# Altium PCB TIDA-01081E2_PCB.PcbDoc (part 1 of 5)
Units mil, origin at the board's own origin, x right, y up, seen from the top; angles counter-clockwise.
Board outline 8611.33 x 3169.64 mil, 4 copper layers (Top Layer, VCC, GND, Bottom Layer), stack 61.6 mil thick; 411 components, 187 nets, 1087 pads, 1987 vias.
Unrouted connection lines stored in the file: 7.
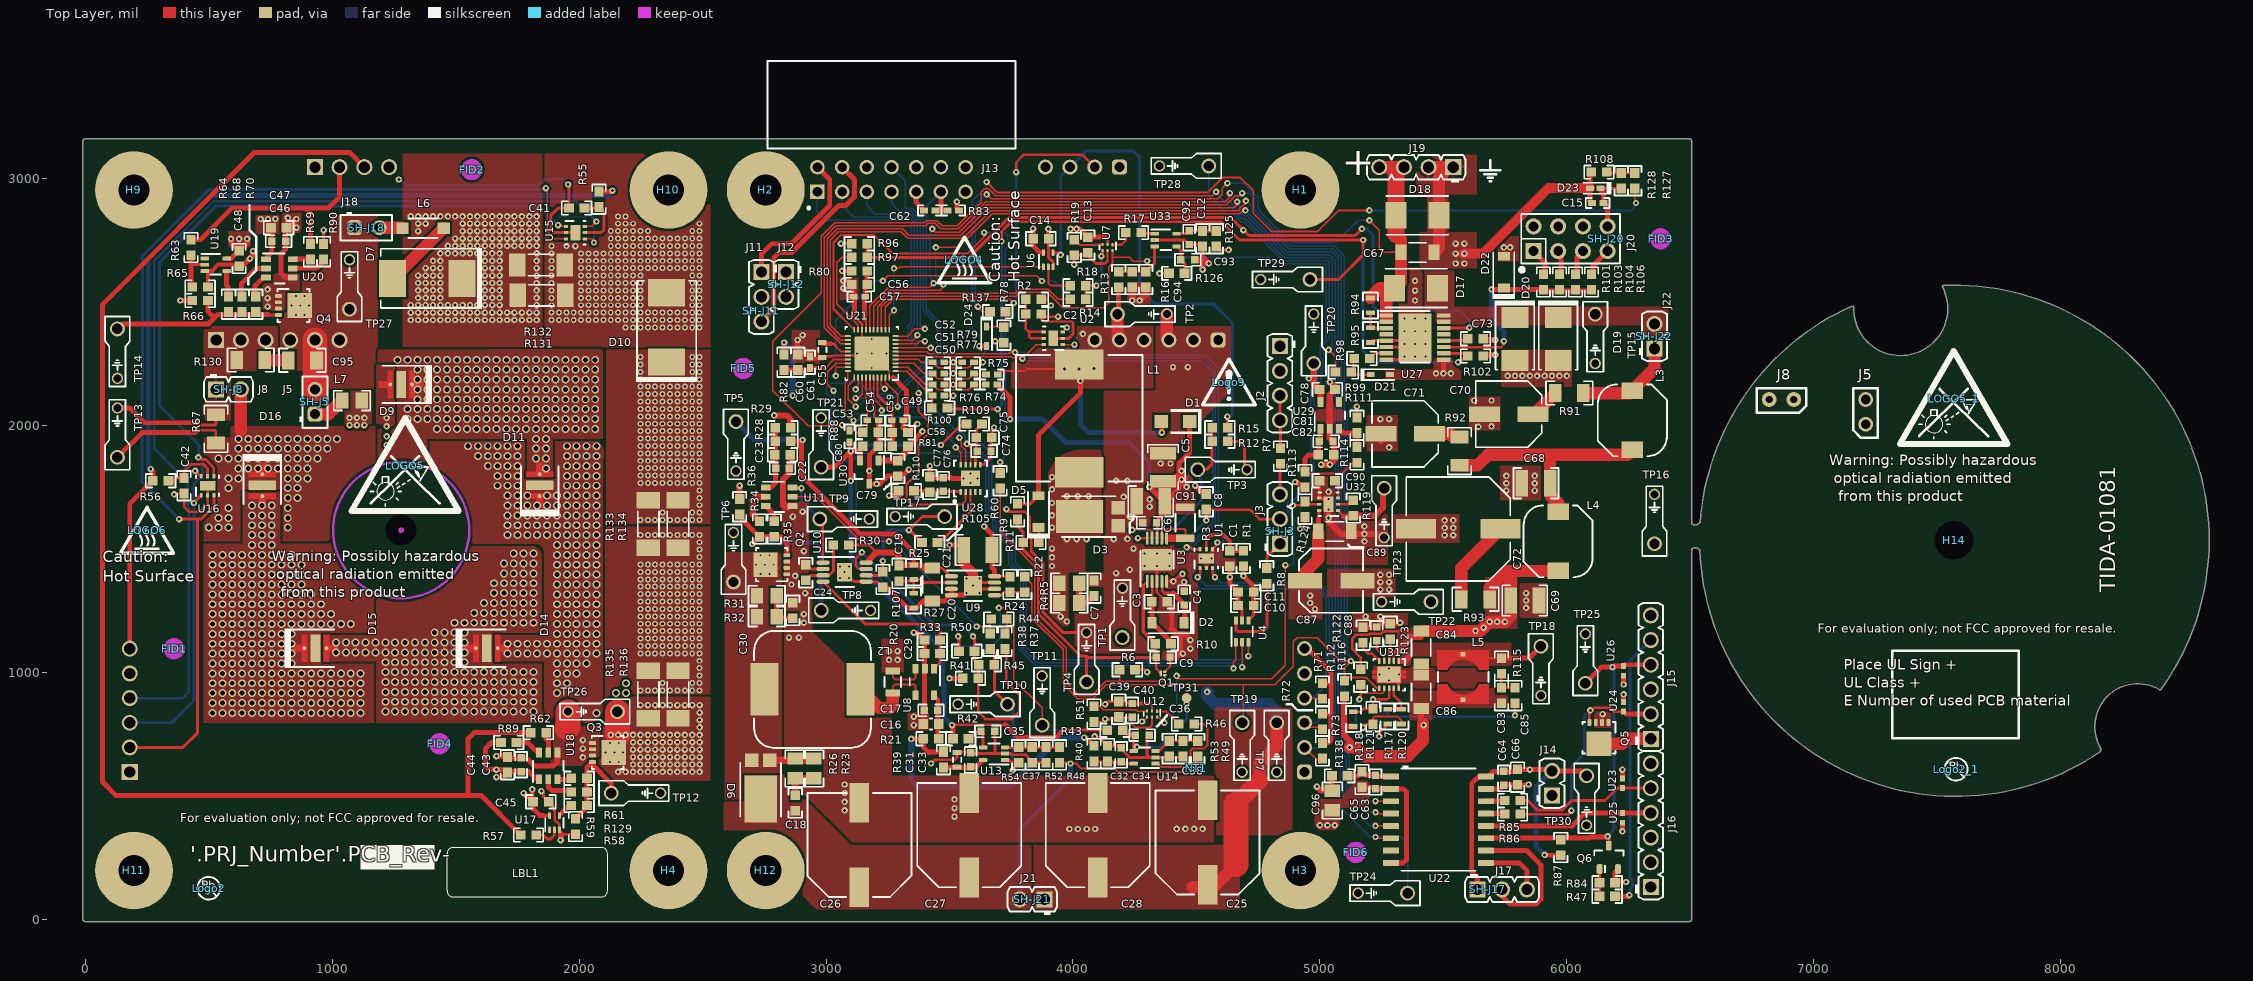
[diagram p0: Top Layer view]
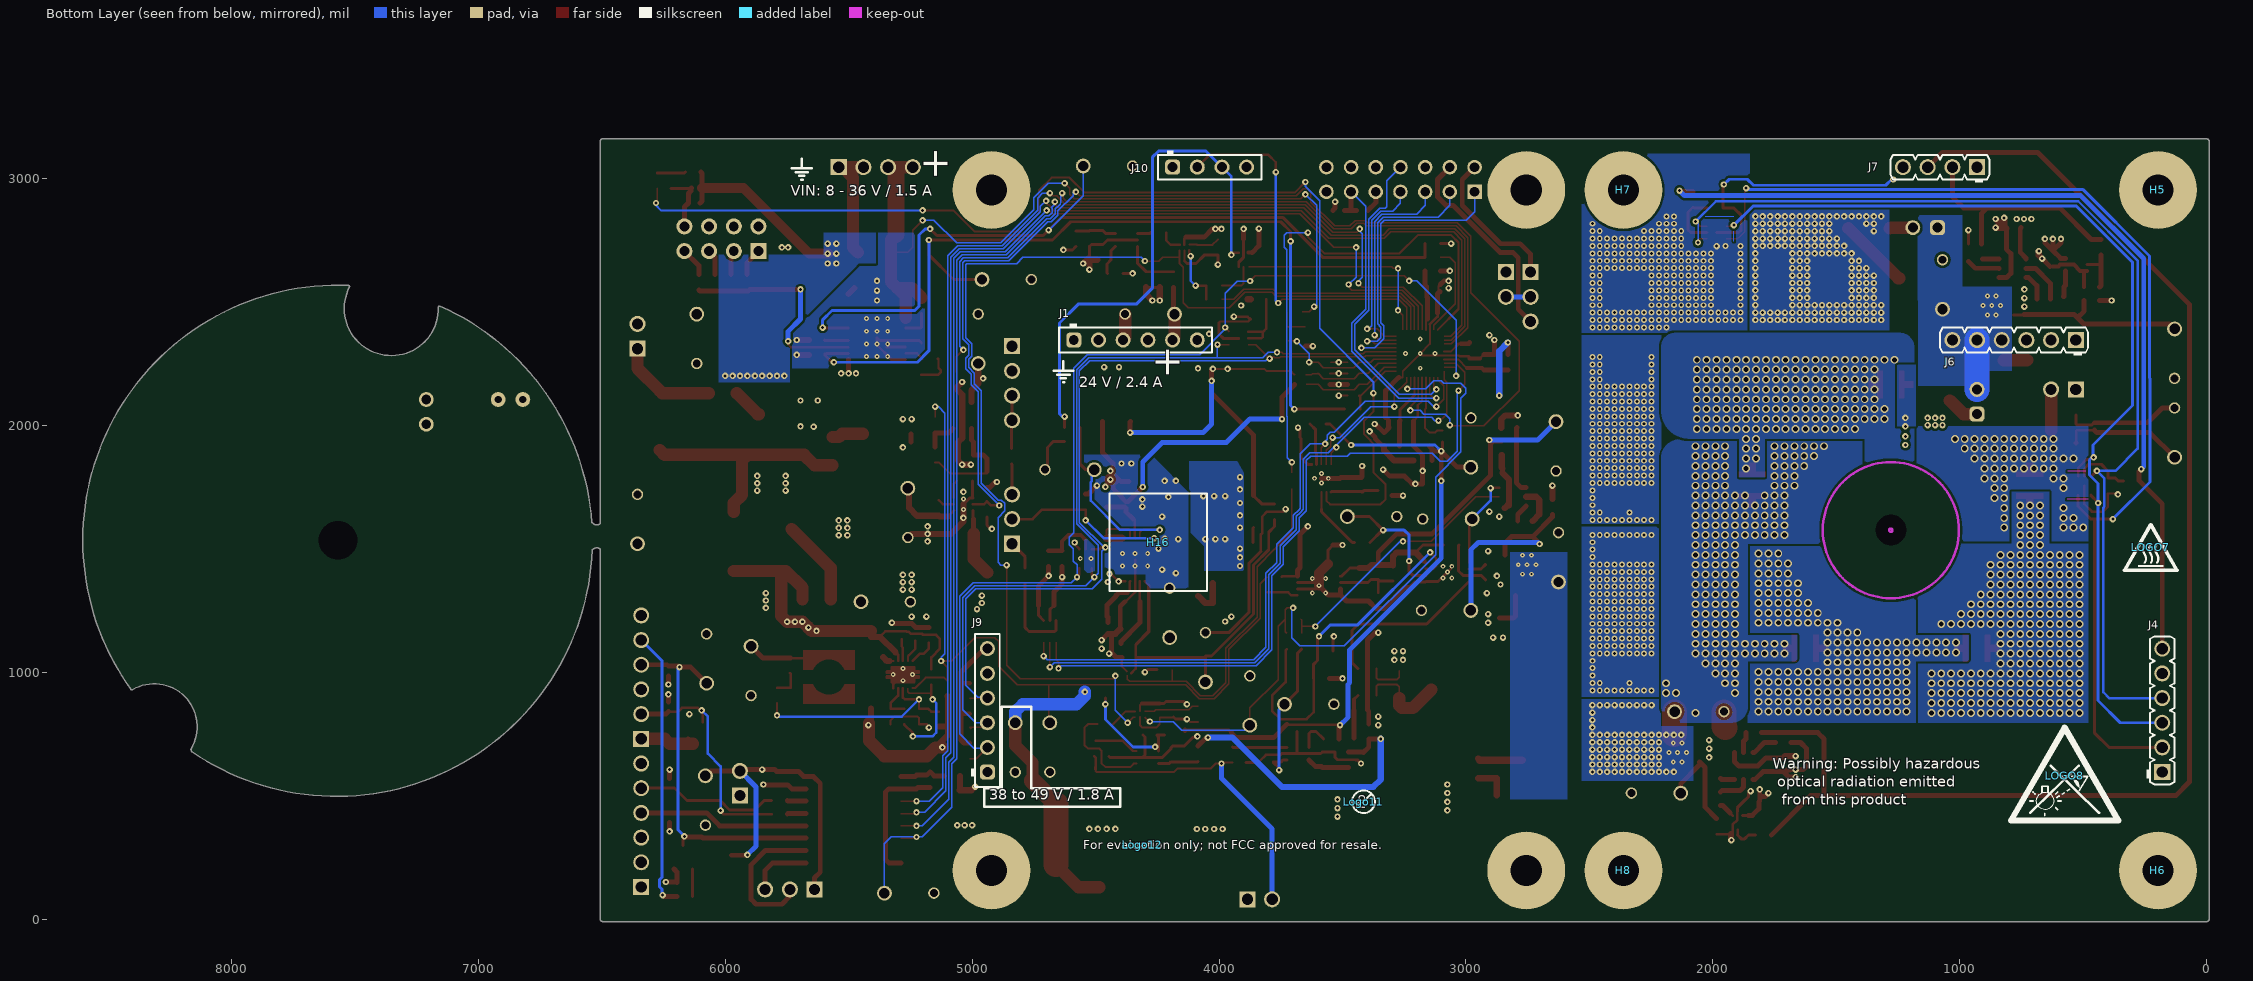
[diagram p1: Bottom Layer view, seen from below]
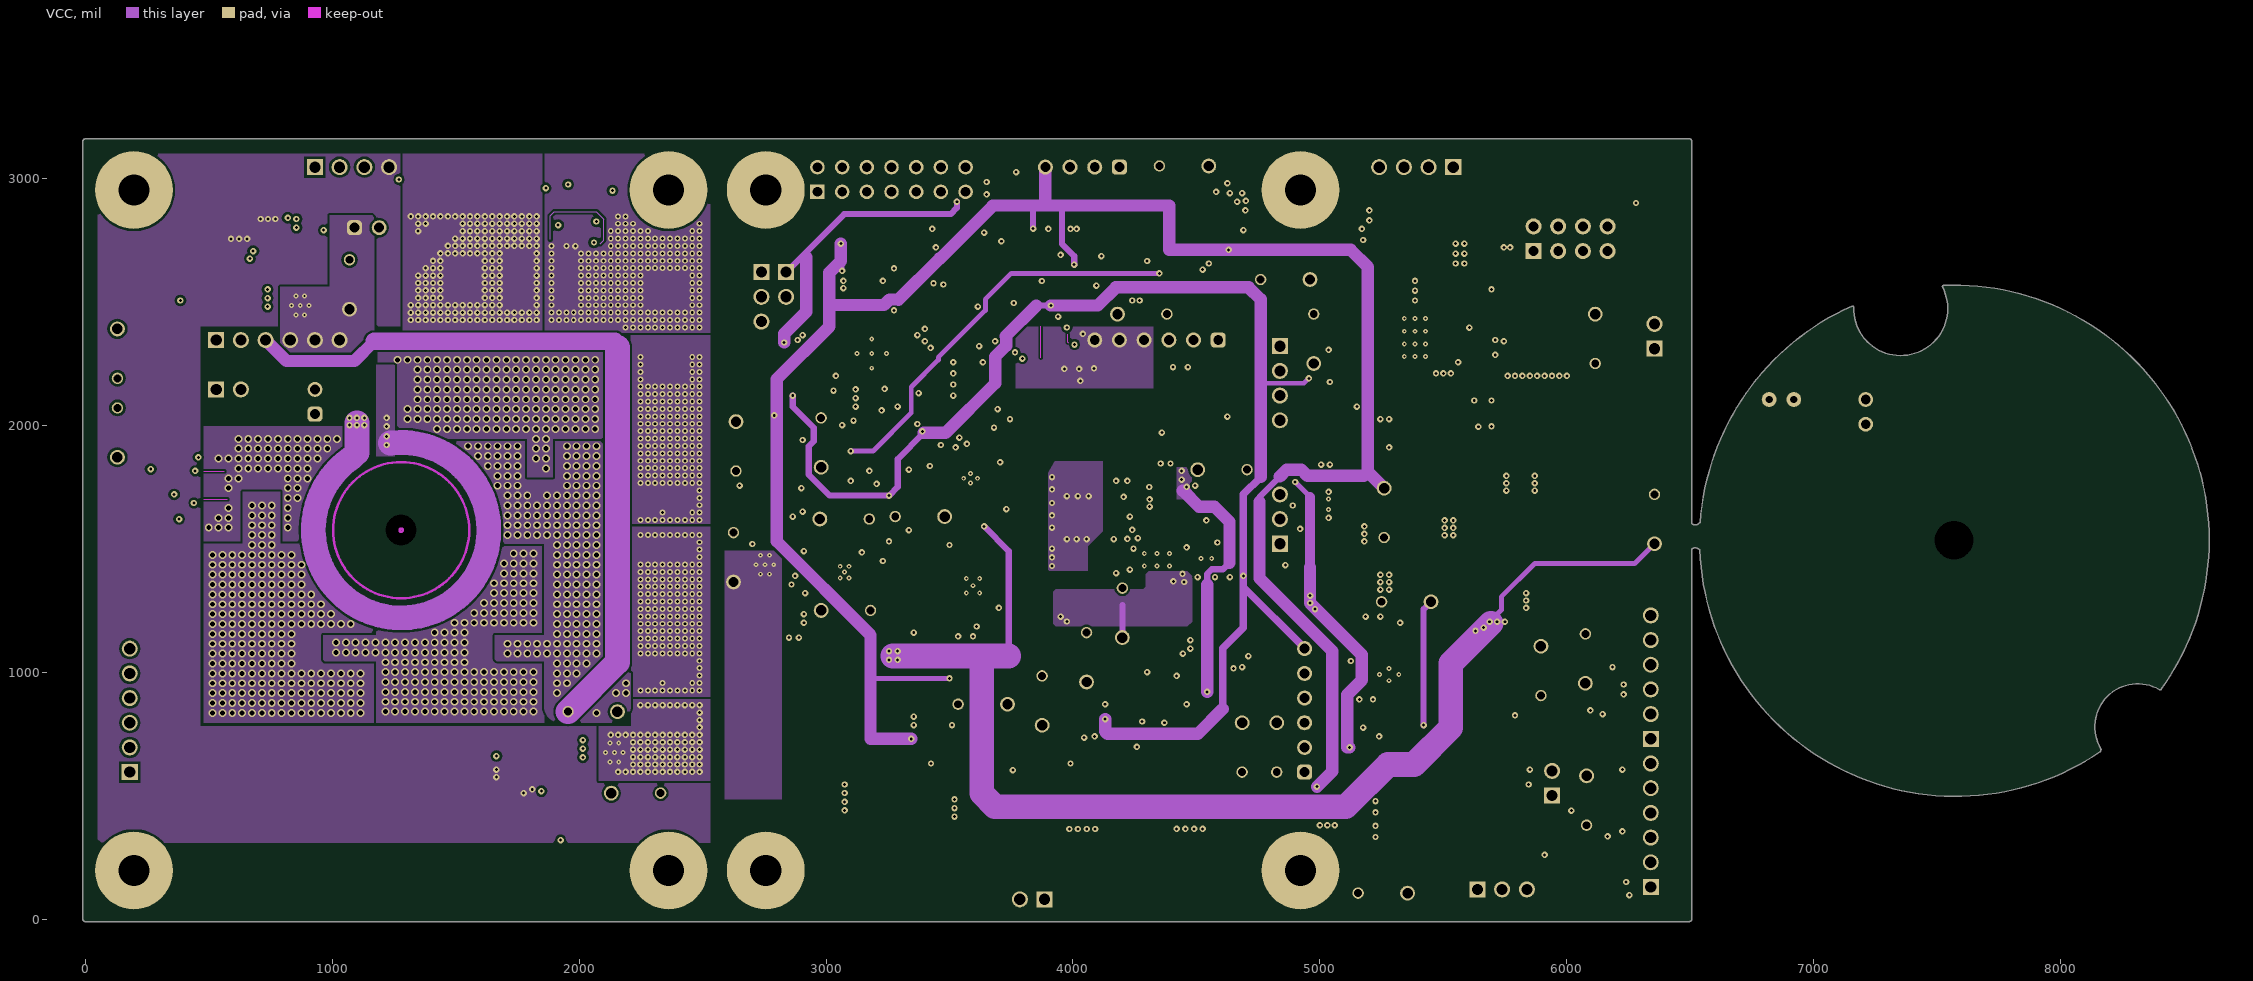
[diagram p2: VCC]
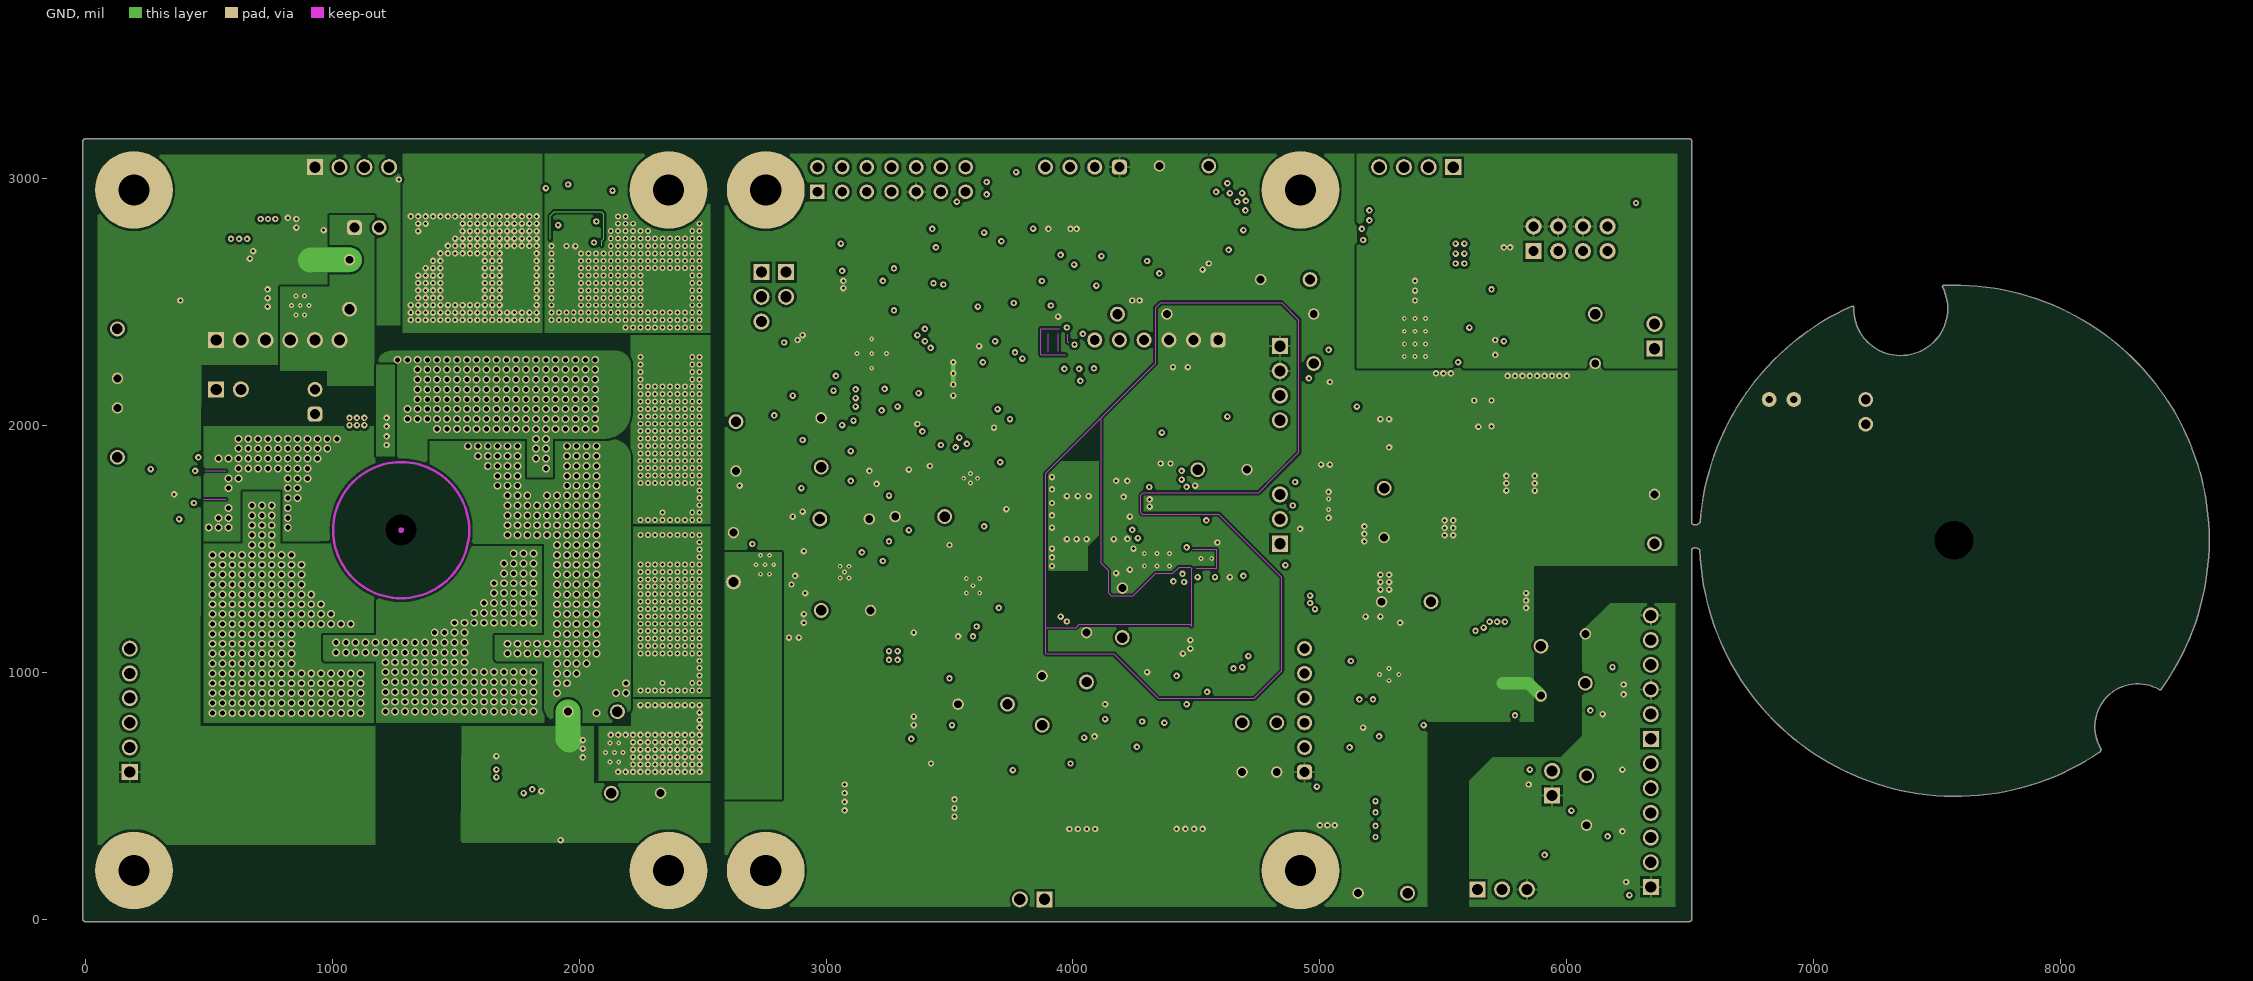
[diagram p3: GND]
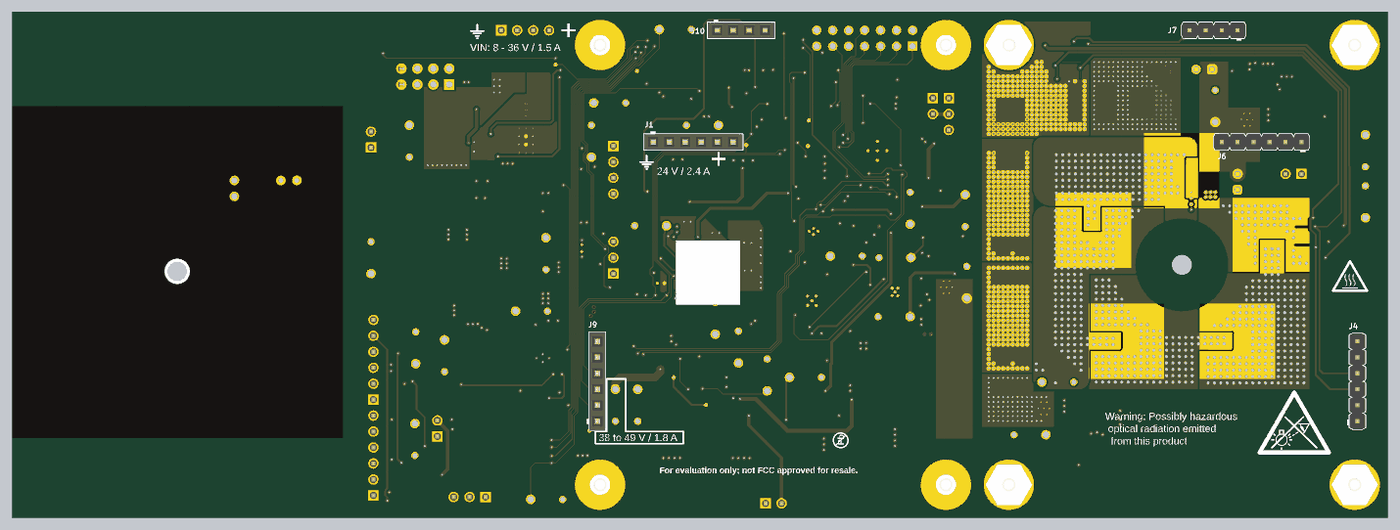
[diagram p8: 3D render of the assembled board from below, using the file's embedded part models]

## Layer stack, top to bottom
Top Solder: solder mask 0.4, Solder Resist, Dk 3.5
Top Layer: signal copper 1.4
Dielectric 1: prepreg 8, FR-4, Dk 4.2
VCC: signal copper 1.4
Dielectric 2: core 40, FR-4, Dk 4.2
GND: signal copper 1.4
Dielectric 3: prepreg 8, FR-4, Dk 4.2
Bottom Layer: signal copper 1.4
Bottom Solder: solder mask 0.4, Solder Resist, Dk 3.5

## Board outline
0,-10.02 cw(c0,0) -10.01,0 -10.01,3149.61 cw(c0,3149.61) 0,3159.62 6496.06,3159.62 cw(c6496.06,3149.61) 6506.08,3149.61 cw(c6496.06,3149.61) 6505.02,3145.12 6505.02,1602.2 ccw(c6520,1620) 6536.45,1603.55 cw(c6540,1600) 6540.18,1605.01 cw(c7574.8,1534.09) 7154.55,2482.16 cw(c7156.58,2477.58) 7161.6,2477.58 cw(c7156.58,2477.58) 7161.59,2477.42 ccw(c7352.06,2472.52) 7542.58,2472.52 ccw(c7352.06,2472.52) 7521.86,2558.93 ccw(c7352.06,2472.52) 7521.84,2558.96 7521.86,2558.93 cw(c7526.31,2561.23) 7526.11,2566.24 cw(c7568.3,1534.09) 8601.32,1534.09 cw(c7568.3,1534.09) 8407.12,931.17 cw(c8402.66,933.47) 8400.13,929.14 ccw(c8312.24,778.71) 8162.61,689.46 cw(c8158.3,686.89) 8163.31,686.89 cw(c8158.3,686.89) 8161.27,682.85 cw(c8156.42,681.56) 8161.44,681.56 cw(c8156.42,681.56) 8159.25,677.42 cw(c7574.8,1534.09) 6538.49,1495.22 cw(c6540,1500) 6536.45,1496.45 ccw(c6520,1480) 6505.02,1497.8 6505.02,4.49 cw(c6496.06,0) 6506.08,0 cw(c6496.06,0) 6496.06,-10.02

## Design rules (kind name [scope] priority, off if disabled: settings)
AcuteAngle [All] p1: minimum=1.50000000000000E+0001 checktracksonly=FALSE
AssemblyTestPointUsage [All] p1: valid=2
BoardOutlineClearance BoardOutlineClearance_MountingHoles [OnCopper and InComponentClass('Mounting Holes')] p1: gap=30 ignorepadtopadclearanceinfootprint=FALSE
BoardOutlineClearance BoardOutlineClearance_Poly [OnCopper and IsPoly] p2: gap=25 ignorepadtopadclearanceinfootprint=FALSE
BoardOutlineClearance [OnCopper and Not InComponentClass('Logo') and not InComponentClass('FiducialMark') and not InRegion(1000,500,4000,800) and not InPoly] p3: gap=30 ignorepadtopadclearanceinfootprint=FALSE
Clearance Clearance_fiducial [IsKeepOut and InComponentClass('FiducialMark') vs IsPad and InComponentClass('FiducialMark')] p1: gap=0 ignorepadtopadclearanceinfootprint=FALSE
Clearance Clearance_q1 [InComponent('Q1')] p2: gap=3 ignorepadtopadclearanceinfootprint=FALSE except(0: Arc-Hole Track-Hole SMDPad-Hole THPad-Hole Via-Hole Fill-Hole Poly-Hole Region-Hole Text-Hole)
Clearance Clearance_Keepouts [((IsTrack Or IsArc) And Not InPoly) And IsFree and IsKeepOut vs ((IsTrack Or IsArc) And Not InPoly) And IsFree and IsKeepOut] p3: gap=0 ignorepadtopadclearanceinfootprint=FALSE
Clearance Clearance_Poly [InPolygon] p4: gap=10 ignorepadtopadclearanceinfootprint=FALSE except(0: Arc-Hole Track-Hole SMDPad-Hole THPad-Hole Via-Hole Fill-Hole Poly-Hole Region-Hole Text-Hole)
Clearance [All] p5: gap=6 ignorepadtopadclearanceinfootprint=FALSE except(0: Arc-Hole Track-Hole SMDPad-Hole THPad-Hole Via-Hole Fill-Hole Poly-Hole Region-Hole Text-Hole)
ComponentClearance ComponentClearance_screws [InComponent('H*')] p1: gap=0 collisioncheckmode=3 verticalgap=0 showdistances=FALSE
ComponentClearance ComponentClearance_shj12 [InComponent('SH-J12')] p2: gap=0 collisioncheckmode=3 verticalgap=0 showdistances=FALSE
ComponentClearance ComponentClearance_j11 [InComponent('J11')] p3: gap=0 collisioncheckmode=3 verticalgap=0 showdistances=FALSE
ComponentClearance ComponentClearance_j13 [InComponent('J13')] p4: gap=0 collisioncheckmode=3 verticalgap=0 showdistances=FALSE
ComponentClearance ComponentClearance_j17 [InComponent('J17')] p5: gap=0 collisioncheckmode=3 verticalgap=0 showdistances=FALSE
ComponentClearance ComponentClearance_j15 [InComponent('J15')] p6: gap=0 collisioncheckmode=3 verticalgap=0 showdistances=FALSE
ComponentClearance ComponentClearance_j16 [InComponent('J16')] p7: gap=0 collisioncheckmode=3 verticalgap=0 showdistances=FALSE
ComponentClearance ComponentClearance_MountingHoles_FiducialMarks [InComponentClass('Mounting Holes') vs InComponentClass('FiducialMark')] p8: gap=50 collisioncheckmode=3 verticalgap=10 showdistances=FALSE
ComponentClearance ComponentClearance_Shunt [InComponentClass('Header') vs InComponentClass('Shunt')] p9: gap=0 collisioncheckmode=3 verticalgap=0 showdistances=FALSE
ComponentClearance ComponentClearance_Logo [InComponentClass('Logo')] p10: gap=50 collisioncheckmode=3 verticalgap=10 showdistances=FALSE
ComponentClearance ComponentClearance_ScrewToNut [(HasFootprint('NY PMS 440 0025 PH')) vs (HasFootprint('Keystone_1902C'))] p11: gap=5 collisioncheckmode=3 verticalgap=10 showdistances=FALSE
ComponentClearance ComponentClearance_MountingHoles [InComponentClass('Mounting Holes')] p12: gap=30 collisioncheckmode=3 verticalgap=100000 showdistances=FALSE
ComponentClearance ComponentClearance_SmallPassives [HasFootprint('0201*') or HasFootprint('0402*') or HasFootprint('0508') or HasFootprint('0603*') or HasFootprint('0612') or HasFootprint('0805*') or HasFootprint('0815*') or HasFootprint('0830*') or HasFootprint('1206*') or HasFootprint('1210*') or HasFootprint('1808*') or HasFootprint('1812*') or HasFootprint('1825*') or HasFootprint('2010*') or HasFootprint('2220*') or HasFootprint('2225*') or HasFootprint('2512*') or HasFootprint('2728*') or HasFootprint('3518*') vs HasFootprint('0201*') or HasFootprint('0402*') or HasFootprint('0508') or HasFootprint('0603*') or HasFootprint('0612') or HasFootprint('0805*') or HasFootprint('0815*') or HasFootprint('0830*') or HasFootprint('1206*') or HasFootprint('1210*') or HasFootprint('1808*') or HasFootprint('1812*') or HasFootprint('1825*') or HasFootprint('2010*') or HasFootprint('2220*') or HasFootprint('2225*') or HasFootprint('2512*') or HasFootprint('2728*') or HasFootprint('3518*')] p13: gap=14.96 collisioncheckmode=3 verticalgap=10 showdistances=FALSE
ComponentClearance ComponentClearance_THtoSMT [IsThruComponent vs IsSMTComponent] p14: gap=30 collisioncheckmode=3 verticalgap=30 showdistances=FALSE
ComponentClearance ComponentClearance_THtoTH [IsThruComponent vs IsThruComponent] p15: gap=30 collisioncheckmode=3 verticalgap=30 showdistances=FALSE
ComponentClearance [All] p16: gap=30 collisioncheckmode=3 verticalgap=10 showdistances=FALSE
DiffPairsRouting [All] p1: maxlimit=100 minlimit=10 mostfreqgap=10 toplayer_minwidth=15 toplayer_maxwidth=15 toplayer_prefwidth=15 midlayer1_minwidth=15 midlayer1_maxwidth=15 midlayer1_prefwidth=15 midlayer2_minwidth=15 midlayer2_maxwidth=15 midlayer2_prefwidth=15 bottomlayer_minwidth=15 bottomlayer_maxwidth=15 bottomlayer_prefwidth=15 maxuncoupledlength=1000
FabricationTestPointUsage TestPointUsage [All] p1: valid=2 allowmultiple=FALSE
FabricationTestpoint Testpoint [All] p1: side=3 testpointundercomponent=TRUE minsize=40 maxsize=100 preferedsize=60 minholesize=0 maxholesize=40 preferedholesize=32 testpointgrid=1 allowsidetop=TRUE allowsidebottom=TRUE usegrid=TRUE gridtolerance=0.01
FanoutControl Fanout_LCC [IsLCC] p1: bgadir=Out bgaviamode=Centered fanoutstyle=Auto fanoutdirection=Alternating viagrid=1 // Fanout_LCC (Default Rule)
FanoutControl Fanout_BGA [IsBGA] p2: bgadir=Out bgaviamode=Centered fanoutstyle=Auto fanoutdirection=Alternating viagrid=1 // Fanout_BGA (Default Rule)
FanoutControl Fanout_Default [All] p4: bgadir=Out bgaviamode=Centered fanoutstyle=Auto fanoutdirection=Alternating viagrid=1 // Fanout_Default (Default Rule)
FanoutControl Fanout_Small [(CompPinCount < 5)] p5: bgadir=Out bgaviamode=Centered fanoutstyle=Auto fanoutdirection=OutThenIn viagrid=1 // Fanout_Small (Default Rule)
HoleSize [All] p1: absolutevalues=TRUE maxlimit=251 minlimit=7.87 maxpercent=80.000 minpercent=20.000
MinimumAnnularRing MinimumAnnularRing_ThermalPadVias [IsVia and InAnyComponent] p1: minimumring=5.91
MinimumAnnularRing [All] p2: minimumring=6
MinimumSolderMaskSliver MinimumSolderMaskSliver_Logo [InComponentClass('Logo') vs InComponentClass('Logo')] p1: minsoldermaskwidth=0.7
MinimumSolderMaskSliver [All] p2: minsoldermaskwidth=3
PlaneConnect [All] p1: planeconnectstyle=Direct reliefexpansion=10 reliefentries=4 reliefconductorwidth=10 reliefairgap=10
PolygonConnect PolygonConnect_j22 [InComponent('J22')] p1: connectstyle=Direct reliefconductorwidth=10 reliefentries=4 polygonreliefangle="90 Angle" airgapwidth=10
PolygonConnect PolygonConnect_j21 [InComponent('J21');] p2: connectstyle=Direct reliefconductorwidth=10 reliefentries=4 polygonreliefangle="90 Angle" airgapwidth=10
PolygonConnect PolygonConnect_j18 [InComponent('J18');] p3: connectstyle=Direct reliefconductorwidth=10 reliefentries=4 polygonreliefangle="90 Angle" airgapwidth=10
PolygonConnect PolygonConnect_j6 [InComponent('J6');] p4: connectstyle=Direct reliefconductorwidth=10 reliefentries=4 polygonreliefangle="90 Angle" airgapwidth=10
PolygonConnect PolygonConnect_j7 [InComponent('J7');] p5: connectstyle=Direct reliefconductorwidth=10 reliefentries=4 polygonreliefangle="90 Angle" airgapwidth=10
PolygonConnect PolygonConnect_j1 [InComponent('J1');] p6: connectstyle=Direct reliefconductorwidth=10 reliefentries=4 polygonreliefangle="90 Angle" airgapwidth=10
PolygonConnect PolygonConnect_tp [InComponent('TP*');] p7: connectstyle=Direct reliefconductorwidth=10 reliefentries=4 polygonreliefangle="90 Angle" airgapwidth=10
PolygonConnect PolygonConnect_buckvout [InNet('BUCK_VOUT')] p8: connectstyle=Direct reliefconductorwidth=10 reliefentries=4 polygonreliefangle="90 Angle" airgapwidth=10
PolygonConnect PolygonConnect_THT [All vs IsThruPin] p9: connectstyle=Relief reliefconductorwidth=10 reliefentries=4 polygonreliefangle="90 Angle" airgapwidth=10
PolygonConnect [All] p10: connectstyle=Direct reliefconductorwidth=10 reliefentries=4 polygonreliefangle="90 Angle" airgapwidth=10
RoutingVias ThermalPadVias [IsVia and InAnyComponent] p1: holewidth=7.87 width=19.68 viastyle="Through Hole" minholewidth=7.87 minwidth=19.68 maxholewidth=12.99 maxwidth=23.62
RoutingVias [All] p2: holewidth=12 width=26 viastyle="Through Hole" minholewidth=8 minwidth=24 maxholewidth=40 maxwidth=65
SilkToBoardRegionClearance [Not ((IsComment or IsDesignator) And (Hide <> 'False')) and not InRegion(1000,500,4000,800)] p1:
SilkToSilkClearance SilkToSilkClearance_Pb-FreeLogo [(HasFootprint('Pb-Free_Overlay_Medium') OR HasFootprint('Pb-Free_Overlay_Small')) vs (HasFootprint('Pb-Free_Overlay_Medium') OR HasFootprint('Pb-Free_Overlay_Small'))] p1: silktosilkclearance=0
SilkToSilkClearance [All] p2: silktosilkclearance=2
SilkToSolderMaskClearance SilkToComponentPadClearance [(IsPad or IsFill or IsRegion) and InAnycomponent] p1: minsilkscreentomaskgap=2 clearancetoexposedcopper=TRUE
SilkToSolderMaskClearance "Silk to Solder Mask Opening" [All] p2: minsilkscreentomaskgap=2 clearancetoexposedcopper=FALSE
SolderMaskExpansion SolderMaskExpansion_via [IsVia] p1: expansion=-8
SolderMaskExpansion [All] p2: expansion=2
Width [All] p1: maxlimit=100 minlimit=6 preferedwidth=10 checkconnectedcopper=TRUE
15 further rules are at their usual default settings.

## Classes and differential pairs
component class TIDA-01081E2_CommonPower: C15 C67 C68 C69 C70 C71 C72 C73 C74 C75 C76 C77 C78 C79 C80 C81 C82 C83 C84 C85 C86 C87 C88 C89 C90 D17 D18 D19 D20 D21 D22 D23 J19 J20 J22 L3 L4 L5 R91 R92 R93 R94 R95 R96 R97 R98 R99 R100 R101 R102 R103 R104 R105 R106 R107 R108 R109 R110 R111 R112 R113 R114 R115 R116 R117 R118 R119 R120 R121 R122 R123 R124 R127 R128 SH-J20 SH-J22 TP15 TP16 TP17 TP18 TP19 TP20 TP21 TP22 TP23 TP28 TP29 U27 U28 U29 U30 U31 U32
component class TIDA-01081E2_DigitalIO: C63 C64 C65 C66 C96 J14 J15 J16 J17 Q5 Q6 R47 R84 R85 R86 R87 R138 SH-J17 TP24 TP25 TP30 U22 U23 U24 U25 U26
component class TIDA-01081E2_Controller: C49 C50 C51 C52 C53 C54 C55 C56 C57 C58 C59 C60 C61 C62 D24 J9 J10 J11 J12 J13 R71 R72 R73 R74 R75 R76 R77 R78 R79 R80 R81 R82 R83 R88 R137 SH-J11 SH-J12 U21
component class TIDA-01081E2_LED_Board: C41 C42 C43 C44 C45 C46 C47 C48 C95 D7 D9 D10 D11 D14 D15 D16 J4 J5 J6 J7 J8 J18 L6 L7 Q3 Q4 R55 R56 R57 R58 R59 R61 R62 R63 R64 R65 R66 R67 R68 R69 R70 R89 R90 R129 R130 R131 R132 R133 R134 R135 R136 SH-J5 SH-J8 SH-J18 TP12 TP13 TP14 TP26 TP27 U15 U16 U17 U18 U19 U20
component class TIDA-01081E2_Pre-Boost: C16 C17 C18 C19 C20 C21 C22 C23 C24 C25 C26 C27 C28 C29 C30 C31 C32 C33 C34 C35 C36 C37 C38 C39 C40 D6 J21 L2 NT1 Q2 R20 R21 R22 R23 R24 R25 R26 R27 R28 R29 R30 R31 R32 R33 R34 R35 R36 R37 R38 R39 R40 R41 R42 R43 R44 R45 R46 R48 R49 R50 R51 R52 R53 R54 SH-J21 TP5 TP6 TP7 TP8 TP9 TP10 TP11 TP31 U8 U9 U10 U11 U12 U13 U14
component class Shunt: SH-J3 SH-J5 SH-J8 SH-J11 SH-J12 SH-J17 SH-J18 SH-J20 SH-J21 SH-J22
component class Header: J2 J3 J4 J5 J6 J7 J8 J11 J12 J14 J15 J16 J17 J18 J19 J20 J21 J22
component class Label: LBL1
component class AssemblyNote: ZZ1 ZZ2 ZZ3 ZZ4 ZZ5 ZZ6 ZZ7 ZZ8 ZZ9 ZZ10 ZZ11 ZZ12 ZZ13 ZZ14 ZZ?
component class FiducialMark: FID1 FID2 FID3 FID4 FID5 FID6
component class TIDA-01081E2_EVM_Hardware: FID1 FID2 FID3 FID4 FID5 FID6 H1 H2 H3 H4 H5 H6 H7 H8 H9 H10 H11 H12 H14 LBL1 Logo2 Logo3 LOGO4 LOGO5 LOGO6 LOGO7 LOGO8 Logo9 LOGO10 Logo11 Logo12 ZZ1 ZZ2 ZZ3 ZZ4 ZZ5 ZZ6 ZZ7 ZZ8 ZZ9 ZZ10 ZZ11 ZZ12 ZZ13 ZZ14 ZZ?
component class TIDA-01081E2_LED_Buck: C1 C2 C3 C4 C5 C6 C7 C8 C9 C10 C11 C12 C13 C14 C91 C92 C93 C94 D1 D2 D3 D5 H16 J1 J2 J3 L1 Q1 R1 R2 R3 R4 R5 R6 R7 R8 R9 R10 R11 R12 R13 R14 R15 R16 R17 R18 R19 R60 R125 R126 SH-J3 TP1 TP2 TP3 TP4 U1 U2 U3 U4 U6 U7 U33

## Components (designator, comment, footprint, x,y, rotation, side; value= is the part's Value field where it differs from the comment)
C1 "GRM188R71C105KE15D" 0603 4635,1460 r270 top value=1uF
C2 "GRM188R71C105KE15D" 0603 3840,2450 r0 top value=1uF
C3 "GRM188R71C105KE15D" 0603 4350,1285 r0 top value=1uF
C4 "GCM188R71C104KA37J" 0603_HV 4450,1300 r270 top value=0.1uF
C5 "GRM32ER71K475KE14L" 1210_270 4365,1830 r90 top value=4.7uF
C6 "GRM188R72A104KA35D" 0603_HV 4310,1605 r180 top value=0.1uF
C7 "CGA3E2X7R2A222K080AA" 0603 4085,1340 r90 top value=2200pF
C8 "GCM1885C1H471JA16D" 0603 4540,1690 r90 top value=470pF
C9 "GCM1885C1H471JA16D" 0603_HV 4365,1060 r0 top value=470pF
C10 "C0603C104K8RACTU" 0603 4700,1270 r180 top value=0.1uF
C11 "GRM188Z71A106MA73D" 0603 4700,1325 r180 top value=10uF
C12 "GRM188R71C105KE15D" 0603 4525,2755 r90 top value=1uF
C13 "GRM188R71C105KE15D" 0603 4060,2730 r270 top value=1uF
C14 "GRM188R71C105KE15D" 0603 3870,2755 r180 top value=1uF
C15 "C1005X7R1C103K050BA" 0402 6125,2900 r180 top value=0.01uF
C16 "ZRB18AD71A106KE01L" 0603_120 3425,790 r180 top value=10uF
C17 "GCM188R71C104KA37J" 0603_HV 3425,845 r0 top value=0.1uF
C18 "CGA3E2X7R2A222K080AA" 0603 2875,470 r270 top value=2200pF
C19 "CL10B103KB8NCNC" 0603 3295,1400 r270 top value=0.01uF
C20 "GRM31CR61E226KE15L" 1206_180 3430,1355 r270 top value=22uF
C21 "GRM32ER71K475KE14L" 1210_270 3615,1495 r180 top value=4.7uF
C22 "GCM188R71C104KA37J" 0603_HV 2823.5,1825 r180 top value=0.1uF
C23 "GRM188R71C105KE15D" 0603 2823.5,1880 r180 top value=1uF
C24 "GRM188R71C105KE15D" 0603 2917.59,1403.19 r90 top value=1uF
C25 "EEE-FK1J101P" SM_RADIAL_G 4545,310 r90 top value=100uF
C26 "EEE-FK1J101P" SM_RADIAL_G 3135,300 r90 top value=100uF
C27 "EEE-FK1J101P" SM_RADIAL_G 3580,340 r90 top value=100uF
C28 "EEE-FK1J101P" SM_RADIAL_G 4100,340 r90 top value=100uF
C29 "CGA3E2C0G1H470J080AA" 0603 3430,1075 r180 top value=47pF
C30 "CGA3E2X7R2A222K080AA" 0603 2865,1250 r90 top value=2200pF
C31 "GRM188R71C105KE15D" 0603S 3530.31,645 r270 top value=1uF
C32 "GRM188R71C105KE15D" 0603 4140,670 r270 top value=1uF
C33 "GCM188R71C104KA37J" 0603_HV 3585.31,645 r270 top value=0.1uF
C34 "GCM188R71C104KA37J" 0603_HV 4195,665 r270 top value=0.1uF
C35 "GCM188R71C104KA37J" 0603_HV 3655.31,760 r0 top value=0.1uF
C36 "GCM188R71C104KA37J" 0603_HV 4280,745 r0 top value=0.1uF
C37 "C0603C151J5GACTU" 0603 3835,665 r90 top value=150pF
C38 "06035A101JAT2A" 0603 4390,690 r90 top value=100pF
C39 "GRM188R71C105KE15D" 0603 4185,850 r270 top value=1uF
C40 "GCM188R71C104KA37J" 0603_HV 4240,845 r90 top value=0.1uF
C41 "GRM188R71C105KE15D" 0603 1990,2880 r180 top value=1uF
C42 "GRM188R71C105KE15D" 0603 400,1755 r270 top value=1uF
C43 "GCM188R71C104KA37J" 0603_HV 1765,625 r270 top value=0.1uF
C44 "GRM188R71C105KE15D" 0603 1710,625 r270 top value=1uF
C45 "GRM188R71C105KE15D" 0603 1845,475 r180 top value=1uF
C46 "GCM188R71C104KA37J" 0603_HV 783.11,2745 r180 top value=0.1uF
C47 "GRM188R71C105KE15D" 0603 783.11,2800 r180 top value=1uF
C48 "GRM188R71C105KE15D" 0603 623.11,2675 r90 top value=1uF
C49 "C1005X7R1C103K050BA" 0402 3455,2120 r0 top value=0.01uF
C50 "C1005X7R1C103K050BA" 0402 3455,2165 r0 top value=0.01uF
C51 "C1005X7R1C103K050BA" 0402 3455,2210 r0 top value=0.01uF
C52 "C1005X7R1C103K050BA" 0402 3455,2255 r0 top value=0.01uF
C53 "GRM188Z71A106MA73D" 0603 3180,1971.3 r0 top value=10uF
C54 "GRM155R71A104KA01D" 0402 3190,2020 r180 top value=0.1uF
C55 "GRM188R70J474KA01D" 0603S 2985,2305 r270 top value=0.47uF
C56 "GRM188Z71A106MA73D" 0603 3135,2570 r180 top value=10uF
C57 "GRM155R71A104KA01D" 0402 3135,2520 r0 top value=0.1uF
C58 "GRM188Z71A106MA73D" 0603 3300,1970 r0 top value=10uF
C59 "GRM155R71A104KA01D" 0402 3290,2020 r180 top value=0.1uF
C60 "GRM188Z71A106MA73D" 0603 2885,2255 r90 top value=10uF
C61 "GRM155R71A104KA01D" 0402 2935,2255 r270 top value=0.1uF
C62 "GRM155R70J222KA01D" 0402 3420,2870 r180 top value=2200pF
C63 "GCM188R71C104KA37J" 0603_HV 5225,555 r90 top value=0.1uF
C64 "GCM188R71C104KA37J" 0603_HV 5745,570 r90 top value=0.1uF
C65 "GRM188Z71A106MA73D" 0603 5170,565 r270 top value=10uF
C66 "GRM188Z71A106MA73D" 0603 5800,575 r270 top value=10uF
C67 "GRM31CR72A105KA01L" 1206_180 5395,2700 r0 top value=1uF
C68 "GRM32ER71K475KE14L" 1210_270 5875,1765 r180 top value=4.7uF
C69 "GRM32ER71K475KE14L" 1210_270 5830,1290 r0 top value=4.7uF
C70 "EEE-FK1J220XP" SM_RADIAL_D8 5765,2045 r180 top value=22uF
C71 "EEE-FK1J220XP" SM_RADIAL_D8 5345,1965 r180 top value=22uF
C72 "EEE-FK1J101P" SM_RADIAL_G 5560,1580 r180 top value=100uF
C73 "GRM188R71C105KE15D" 0603 5630,2350 r180 top value=1uF
C74 "GCM188R71C104KA37J" 0603_HV 3640,1895 r180 top value=0.1uF
C75 "GRM188R71C105KE15D" 0603 3640,1950 r180 top value=1uF
C76 "GCM188R71C104KA37J" 0603_HV 3475,1760 r270 top value=0.1uF
C77 "GRM188R71C105KE15D" 0603 3420,1760 r270 top value=1uF
C78 "GRM188R71C105KE15D" 0603 5030,2145 r0 top value=1uF
C79 "GRM188R71C105KE15D" 0603 3290,1825 r270 top value=1uF
C80 "GRM188R71C105KE15D" 0603 3180,1915 r0 top value=1uF
C81 "GCM188R71C104KA37J" 0603_HV 5025,1935 r180 top value=0.1uF
C82 "ZRB18AD71A106KE01L" 0603_120 5025,1880 r0 top value=10uF
C83 "C0603C561J5GACTU" 0603 5735,905 r90 top value=560pF
C84 "GRM31CR72A105KA01L" 1206_180 5410,1100 r270 top value=1uF
C85 "C0603C681J5GACTU" 0603 5790,905 r270 top value=680pF
C86 "C3216X5R1E336M160AC" 1206_180 5410,920 r90 top value=33uF
C87 "UUD1A101MCL1GS" SM_RADIAL_6.3AMM 5045,1370 r0 top value=100uF
C88 "GCM188R71C104KA37J" 0603_HV 5230,1155 r270 top value=0.1uF
C89 "C3216X5R1E336M160AC" 1206_180 5060,1570 r0 top value=33uF
C90 "GRM188R71C104KA01D" 0603 5030,1775 r180 top value=0.1uF
C91 "CGA6N3X7R2A225K230AB" 1210_250 4315,1692 r180 top value=2.2uF
C92 "GCM188R71C104KA37J" 0603_HV 4470,2760 r90 top value=0.1uF
C93 "GCM188R71C104KA37J" 0603_HV 4465,2670 r0 top value=0.1uF
C94 "06035A100JAT2A" 0603 4295,2590 r90 top value=10pF
C95 "12061A681JAT2A" 1206 879,2263 r180 top value=680pF
C96 "GRM21BR6YA106KE43L" 0805_HV 5050,480 r270 top value=10uF
D1 "VS-2EFH02HM3/I" DO-219AB 4415,2015 r180 top value=200V
D2 "MMSD4148T1G" SOD-123 4385,1200 r180 top value=100V
D3 "PDS3100Q-13" PowerDI5 4105,1630 r180 top value=100V
D5 "MMSD4148T1G" SOD-123 3860,1650 r90 top value=100V
D6 "PDS3100Q-13" PowerDI5 2735,565 r270 top value=100V
D7 "MBRS340T3G" SMC 1385,2595 r180 top value=40V
D9 "LUW HWQP-8M7N-EBVF46FCBB46-8E8H" LUW_HWQP_White-IHT 1279,2165 r90 top value=White
D10 "MBRS340T3G" SMC 2354,2396 r90 top value=40V
D11 "LUW HWQP-8M7N-EBVF46FCBB46-8E8H" LUW_HWQP_White-IHT 1840,1757 r0 top value=White
D14 "LUW HWQP-8M7N-EBVF46FCBB46-8E8H" LUW_HWQP_White-IHT 1626,1097 r270 top value=White
D15 "LUW HWQP-8M7N-EBVF46FCBB46-8E8H" LUW_HWQP_White-IHT 932,1097 r270 top locked value=White
D16 "LUW HWQP-8M7N-EBVF46FCBB46-8E8H" LUW_HWQP_White-IHT 717,1757 r180 top value=White
D17 "SM6T42CAY" SMB-Bi 5390,2555 r0 top value=36V
D18 "SM6T42CAY" SMB-Bi 5395,2850 r180 top value=36V
D19 "SM6T42AY" SMB 5965,2350 r270 top value=36V
D20 "VSSB310-E3/52T" SMB 5790,2350 r270 top value=100V
D21 "1N4148WT" Fairchild_SOD-523F 5245,2205 r0 top value=75V
D22 "MMSZ4683T1G" SOD-123 5745,2620 r90 top value=3V
D23 "RB521S30T1G" SOD-523 6115,2960 r180 top value=30V
D24 "1N4148WT" Fairchild_SOD-523F 3650,2360 r270 top value=75V
FID1 "Fiducial" Fiducial10-20 360,1095 r0 top
FID2 "Fiducial" Fiducial10-20 1565,3035 r0 top
FID3 "Fiducial" Fiducial10-20 6380,2755 r0 top
FID4 "Fiducial" Fiducial10-20 1435,710 r0 top
FID5 "Fiducial" Fiducial10-20 2665,2230 r0 top
FID6 "Fiducial" Fiducial10-20 5145,270 r0 top
H1 "4802" Keystone_4802 4921.26,2952.76 r0 top
H2 "4802" Keystone_4802 2755.91,2952.76 r0 top
H3 "4802" Keystone_4802 4921.26,196.85 r0 top
H4 "4802" Keystone_4802 2362.2,196.85 r0 top
H5 "1902C" Keystone_1902C#1 197.21,2952.76 r180 bottom
H6 "1902C" Keystone_1902C#1 197.21,196.85 r180 bottom
H7 "1902C" Keystone_1902C#1 2362.56,2952.76 r180 bottom
H8 "1902C" Keystone_1902C#2 2362.2,196.85 r180 bottom locked
H9 "4802" Keystone_4802 196.85,2952.76 r0 top locked
H10 "4802" Keystone_4802 2361.22,2952.76 r270 top locked
H11 "4802" Keystone_4802 196.85,196.85 r90 top
H12 "4802" Keystone_4802 2755.91,196.85 r0 top
H14 "9080032809" 9080032809 7568.31,1534.09 r0 top
H16 "ICK S 10 X 10 X 6,5" FE_ICK_S10X10X6_5 4246.02,1526.02 r180 bottom
J1 "PPPC061LFBN-RC" Sullins_PPPC061LFBN-RC 4338.11,2345 r180 bottom locked
J2 "61300411121" WURTH_61300411121 4838,2170 r270 top
J3 "61300311121" WURTH_61300311121 4838,1620 r90 top
J4 "61300611121" WURTH_61300611121 180,845 r90 bottom
J5 "TSW-102-17-G-S" Samtec_TSW-102-17-x-S 930,2095 r90 top
J6 "61300611121" WURTH_61300611121 780,2345 r0 bottom
J7 "61300411121" WURTH_61300411121 1080,3045 r0 bottom
J8 "61300211121" WURTH_61300211121 580,2145 r0 top
J9 "PPPC061LFBN-RC" Sullins_PPPC061LFBN-RC 4938,845 r90 bottom
J10 "PPPC041LFBN-RC" Sullins_PPPC041LFBN-RC 4038,3045 r180 bottom
J11 "61300311121" WURTH_61300311121 2738,2520 r270 top
J12 "61300211121" WURTH_61300211121 2838,2570 r270 top
J13 "SBH11-PBPC-D07-RA-BK" Sullins_SBH11-PBPC-D07-RA-BK 3265,2995 r0 top
J14 "61300211121" WURTH_61300211121 5940,550 r90 top
J15 "61300611121" WURTH_61300611121 6340,980 r90 top
J16 "61300611121" WURTH_61300611121 6340,380 r90 top
J17 "61300311121" WURTH_61300311121 5738,120 r0 top
J18 "TSW-102-17-G-S" Samtec_TSW-102-17-x-S 1140,2800 r0 top
J19 "61300411121" WURTH_61300411121 5390,3045 r180 top
J20 "PEC04DAAN" CONN_PEC04DAAN 6015,2755 r0 top
J21 "61300211121" WURTH_61300211121 3834.71,80 r180 top
J22 "61300211121" WURTH_61300211121 6355,2360 r90 top
L1 "744373965101" WE-LHMI_1365 4025,2028 r90 top value=100uH
L2 "7447709471" WE-PD_1210 2945,930 r0 top value=470uH
L3 "CLF7045T-330M" CLF7045 6265,2020 r270 top value=33uH
L4 "CLF7045T-330M" CLF7045 5965,1530 r270 top value=33uH
L5 "744043221" WE-TPC_4828 5580,980 r270 top value=220uH
L6 "742792410" 1806_HighSpeed 1368,2798 r0 top value="60 ohm"
L7 "742792011" 0805_HV 1080,2100 r180 top value="10 ohm"
LBL1 "Size: 0.65\" x 0.20 \"" Label_650x200 1790,190 r0 top
Logo2 "Pb-Free Symbol" Pb-Free_Overlay_Small 500,125 r0 top
Logo2_1 "Pb-Free Symbol" Pb-Free_Overlay_Small 7576.3,607.09 r0 top
Logo3 "FCC disclaimer" FCC_disclaimer 2229.92,6065 r0 top
Logo3_1 "FCC disclaimer" FCC_disclaimer 8519.22,6024.09 r0 top
LOGO4 "CAUTION HOT SURFACE" IEC_HotSurface_Small 3560,2670 r0 top
LOGO5 "LED WARNING" LED_Warning 1295,1835 r0 top
LOGO5_1 "LED WARNING" LED_Warning 7566.3,2107.09 r0 top
LOGO6 "CAUTION HOT SURFACE" IEC_HotSurface_Small 250,1575 r0 top
LOGO7 "CAUTION HOT SURFACE" IEC_HotSurface_Small 226.5,1505.5 r180 bottom
LOGO8 "LED WARNING" LED_Warning 575.39,581.39 r180 bottom
Logo9 "CAUTION.  READ USER GUIDE BEFORE USE" IEC_Caution_Small 4631.67,2174.93 r0 top
Logo11 "Pb-Free Symbol" Pb-Free_Overlay_Small 3415,475 r90 bottom
Logo12 "FCC disclaimer" FCC_disclaimer 4310,300 r180 bottom
NT1 "Net-Tie" Net-Tie_10mil 4500,610 r90 top net-tie
Q1 "CSD15380F3" YJM0003A 4365,995 r180 top value=20V
Q2 "CSD18543Q3A" DNH0008A 2780,1435 r180 top value=60V
Q3 "CSD18543Q3A" DNH0008A 2115,675 r0 top value=60V
Q4 "CSD18543Q3A" DNH0008A 843.11,2485 r0 top value=60V
Q5 "CSD18543Q3A" DNH0008A 6130,735 r270 top value=60V
Q6 "BC817-25,215" SOT-23 6170,250 r90 top value="45 V"
R1 "RC0603FR-07100RL" 0603 4690,1460 r90 top value=100
R2 "RC0603FR-07100RL" 0603 3840,2510 r180 top value=100
R3 "KRL1632E-M-R082-F-T5" KRL1632G8m 4455,1605 r90 top value=0.082
R4 "ERJ-P06F10R0V" 0805_HV 3985,1280 r180 top value=10.0
R5 "ERJ-P06F10R0V" 0805_HV 3985,1360 r180 top value=10.0
R6 "RC0603FR-0710KL" 0603 4220,1010 r180 top value=10.0k
R7 "RC0603FR-074K87L" 0603 4840,1875 r270 top value=4.87k
R8 "RC0603FR-074K87L" 0603 4785,1390 r90 top value=4.87k
R9 "CRCW060321K5FKEA" 0603 3775,1650 r90 top value=21.5k
R10 "RC0603FR-074K87L" 0603 4365,1115 r0 top value=4.87k
R11 "CRCW060321K5FKEA" 0603 3830,1525 r0 top value=21.5k
R12 "RC0603FR-0710KL" 0603 4595,1935 r180 top value=10.0k
R13 "CRCW060334K8FKEA" 0603 4185,2590 r270 top value=34.8k
R14 "RC0603FR-0751R1L" 0603 4020,2510 r0 top value=51.1
R15 "RC0603FR-0751R1L" 0603 4595,1990 r0 top value=51.1
R16 "CRCW06033K74FKEA" 0603 4240,2590 r90 top value=3.74k
R17 "RC0603FR-0751R1L" 0603 4245,2780 r0 top value=51.1
R18 "RC0603FR-0751R1L" 0603 4020,2565 r0 top value=51.1
R19 "RC0603JR-070RL" 0603 4005,2720 r90 top value=0
R20 "KRL1220E-M-R100-F-T5" KRL1220 3270,960 r270 top value=0.1
R21 "RC0603FR-0710RL" 0603 3425,730 r0 top value=10.0
R22 "RC0603FR-071KL" 0603 3805,1355 r270 top value=1.00k
R23 "ERJ-P06F10R0V" 0805_HV 2950,610 r90 top value=10.0
R24 "RC0603FR-071KL" 0603 3745,1355 r270 top value=1.00k
R25 "RR0816P-104-D" 0603_HR 3355,1405 r90 top value=100k
R26 "ERJ-P06F10R0V" 0805_HV 2875,610 r90 top value=10.0
R27 "RR0816P-2152-D-33C" 0603_HR 3355,1290 r90 top value=21.5k
R28 "RC0603JR-070RL" 0603 2825.14,1935 r0 top value=0
R29 "RC0603JR-070RL" 0603 2825.14,1990 r0 top value=0
R30 "RC0603JR-070RL" 0603 3060,1515 r0 top value=0
R31 "ERJ-P06F10R0V" 0805_HV 2760,1310 r180 top value=10.0
R32 "ERJ-P06F10R0V" 0805_HV 2760,1225 r180 top value=10.0
R33 "CRCW06034K22FKEA" 0603 3430,1130 r0 top value=4.22k
R34 "CRCW060315R0JNEA" 0603 2730,1580 r270 top value=15
R35 "CRCW060315R0JNEA" 0603 2790,1580 r270 top value=15
R36 "RC0603FR-0710KL" 0603 2650,1670 r270 top value=10.0k
R37 "RC0603FR-0751R1L" 0603 3725,1125 r90 top value=51.1
R38 "RC0603FR-0751R1L" 0603 3665,1125 r270 top value=51.1
R39 "RC0603FR-0710RL" 0603 3475.31,645 r90 top value=10.0
R40 "RC0603FR-0710RL" 0603 4085,670 r90 top value=10.0
R41 "CRCW060316K9FKEA" 0603 3585,975 r180 top value=16.9k
R42 "RC0603FR-0710KL" 0603 3545.31,730 r180 top value=10.0k
R43 "RC0603FR-0710KL" 0603 4170,765 r180 top value=10.0k
R44 "RC0603FR-0751R1L" 0603 3700,1215 r0 top value=51.1
R45 "CRCW06034K02FKEA" 0603 3650,1030 r180 top value=4.02k
R46 "RC0603FR-0751R1L" 0603 4460,790 r0 top value=51.1
R47 "CRCW060310K0FKEA" 0603 6163.42,91.96 r0 top value=10.0k
R48 "RT0603BRD07100KL" 0603 3945.31,665 r90 top value=100k
R49 "RG1608P-154-B-T5" 0603 4505,690 r90 top value=150k
R50 "CRCW060310K2FKEA" 0603 3570,1085 r0 top value=10.2k
R51 "RC0603JR-070RL" 0603 4085,830 r90 top value=0
R52 "RG1608P-5621-B-T5" 0603 3890.31,665 r90 top value=5.62k
R53 "RT0603BRD077K32L" 0603 4445,690 r90 top value=7.32k
R54 "RT0603DRE07499KL" 0603 3780.31,665 r270 top value=499k
R55 "RC0603FR-07100RL" 0603 2080,2915 r270 top value=100
R56 "RC0603FR-07100RL" 0603 305,1775 r0 top value=100
R57 "RC0603FR-0751R1L" 0603 1795,340 r0 top value=51.1
R58 "RC0603JR-070RL" 0603 2000,460 r0 top value=0
R59 "RC0603FR-0710KL" 0603 1985,375 r90 top value=10.0k
R60 "RC0603JR-070RL" 0603 3705,1775 r90 top value=0
R61 "RC0603FR-073R32L" 0603 2000,570 r0 top value=3.32
R62 "RC0603FR-0751R1L" 0603 1835,755 r0 top value=51.1
R63 "RC0603FR-0751R1L" 0603 428.11,2720 r270 top value=51.1
R64 "RC0603JR-070RL" 0603 580,2490 r270 top value=0
R65 "RC0603FR-07100KL" 0603 465,2560 r180 top value=100k
R66 "RC0603FR-0710KL" 0603 465,2505 r0 top value=10.0k
R67 "ERJ-8BWFR100V" 1206 529,1985 r90 top value=0.1
R68 "RC0603JR-070RL" 0603 635,2490 r270 top value=0
R69 "RC0603FR-0751R1L" 0603 911.57,2702.81 r270 top value=51.1
R70 "RC0603FR-0733RL" 0603 690,2490 r270 top value=33.0
R71 "RC0603FR-074K87L" 0603 5010,923.62 r90 top value=4.87k
R72 "RC0603FR-074K87L" 0603 5010,800 r90 top value=4.87k
R73 "RC0603FR-074K87L" 0603 5010,681.38 r90 top value=4.87k
R74 "CRCW0402240KFKED" 0402 3670,2165 r0 top value=240k
R75 "CRCW0402240KFKED" 0402 3671.38,2205 r0 top value=240k
R76 "CRCW040210K0FKED" 0402 3575,2165 r0 top value=10.0k
R77 "CRCW040210K0FKED" 0402 3575,2210 r0 top value=10.0k
R78 "RC0603FR-07178KL" 0603 3720,2365 r90 top value=178k
R79 "CRCW040210K0FKED" 0402 3575,2255 r0 top value=10.0k
R80 "CRCW060310R0FKEA" 0603 3135,2625 r180 top value=10.0
R81 "CRCW060310R0FKEA" 0603 3300,1915 r0 top value=10.0
R82 "CRCW060310R0FKEA" 0603 2830,2255 r90 top value=10.0
R83 "CRCW040247K0JNED" 0402 3515,2870 r0 top value=47k
R84 "CRCW060310K0FKEA" 0603 6163.42,146.96 r180 top value=10.0k
R85 "CRCW060349R9FKEA" 0603 5780,480 r0 top value=49.9
R86 "CRCW060349R9FKEA" 0603 5780,425 r0 top value=49.9
R87 "CRCW060310K0FKEA" 0603 5975,290 r270 top value=10.0k
R88 "CRCW040210R0FKED" 0402 3095,1955 r270 top value=10.0
R89 "RC0603JR-070RL" 0603 1715,715 r0 top value=0
R90 "RC0603JR-070RL" 0603 965,2702.81 r270 top value=0
R91 "RC1206FR-077R5L" 1206 6010,2130 r0 top value=7.50
R92 "RC1206FR-073R9L" 1206 5565,1895 r270 top value=3.90
R93 "RC1206FR-072RL" 1206 5630,1295 r0 top value=2.00
R94 "RR0816P-1183-D-08D" 0603_HR 5205,2485 r90 top value=118k
R95 "RR0816P-2212-D-34C" 0603_HR 5205,2365 r90 top value=22.1k
R96 "RC0603FR-0749K9L" 0603 3135,2735 r180 top value=49.9k
R97 "RC0603FR-0749K9L" 0603 3135,2680 r180 top value=49.9k
R98 "RC0603FR-0728K7L" 0603 5170,2270 r180 top value=28.7k
R99 "RC0603FR-0710KL" 0603 5095,2215 r0 top value=10.0k
R100 "RC0603FR-07150KL" 0603 3460,2070 r180 top value=150k
R101 "CRCW060323K7FKEA" 0603 5905,2580 r90 top value=23.7k
R102 "CRCW060319K1FKEA" 0603 5630,2280 r180 top value=19.1k
R103 "CRCW060315K4FKEA" 0603 5970,2580 r270 top value=15.4k
R104 "CRCW060311K8FKEA" 0603 6035,2580 r270 top value=11.8k
R105 "CRCW060310K2FKEA" 0603 3420,1525 r180 top value=10.2k
R106 "CRCW06036K65FKEA" 0603 6100,2580 r90 top value=6.65k
R107 "CRCW06032K55FKEA" 0603 3230,1375 r90 top value=2.55k
R108 "CRCW060352K3FKEA" 0603 6130,3025 r0 top value=52.3k
R109 "CRCW060310R0FKEA" 0603 3600,2005 r0 top value=10.0
R110 "CRCW060310R0FKEA" 0603 3325,1735 r0 top value=10.0
R111 "RC0603FR-071KL" 0603 5150,2000 r270 top value=1.00k
R112 "RC0603FR-07100KL" 0603 5100,933.83 r270 top value=100k
R113 "CRCW060310R0FKEA" 0603 4940,1780 r270 top value=10.0
R114 "RC0603FR-071KL" 0603 5150,1880 r90 top value=1.00k
R115 "RC0603FR-07442KL" 0603 5735,1025 r270 top value=442k
R116 "RT0603BRD07200KL" 0603 5165,980 r90 top value=200k
R117 "RR0816P-4422-D-63C" 0603_HR 5275,820 r270 top value=44.2k
R118 "RR0816P-104-D" 0603_HR 5135,810 r270 top value=100k
R119 "RC0603JR-070RL" 0603 5135,1665 r270 top value=0
R120 "RR0816P-8661-D-91H" 0603_HR 5330,820 r90 top value=8.66k
R121 "RT0603DRE0732K4L" 0603 5215,820 r90 top value=32.4k
R122 "RC0603FR-0747KL" 0603 5175,1150 r270 top value=47.0k
R123 "CRCW060324K9FKEA" 0603 5285,1165 r270 top value=24.9k
R124 "RC0603FR-07100KL" 0603 4940,1660 r90 top value=100k
R125 "RC0603FR-0710RL" 0603 4580,2755 r270 top value=10.0
R126 "RC0603FR-0710KL" 0603 4420,2615 r0 top value=10.0k
R127 "RC0603JR-070RL" 0603 6275,2990 r90 top value=0
R128 "CRCW06031K00FKEA" 0603 6220,2990 r270 top value=1.00k
R129 "RC0603FR-0733RL" 0603 2000,515 r0 top value=33.0
R130 "RC1206FR-0735R7L" 1206 670,2264 r0 top value=35.7
R131 "MMB02070C2208FB200" MMB0207 1848,2526 r180 top value=2.20
R132 "MMB02070C2208FB200" MMB0207 1846,2649 r180 top value=2.20
R133 "MMB02070C2208FB200" MMB0207 2280,1600 r90 top value=2.20
R134 "MMB02070C2208FB200" MMB0207 2400,1600 r90 top value=2.20
R135 "MMB02070C2208FB200" MMB0207 2280,910 r90 top value=2.20
R136 "MMB02070C2208FB200" MMB0207 2400,910 r90 top value=2.20
R137 "RC0603FR-0761K9L" 0603 3695,2460 r180 top value=61.9k
R138 "CRCW06031R00JNEA" 0603 5080,580 r180 top value=1.0
SH-J3 "969102-0000-DA" SNT-100-BK-G 4840,1570 r90 top value=1x2
SH-J5 "969102-0000-DA" SNT-100-BK-G 930,2095 r90 top value=1x2
SH-J8 "969102-0000-DA" SNT-100-BK-G 580,2145 r180 top value=1x2
SH-J11 "969102-0000-DA" SNT-100-BK-G 2738,2462.85 r90 top value=1x2
SH-J12 "969102-0000-DA" SNT-100-BK-G 2838.01,2570 r90 top value=1x2
SH-J17 "969102-0000-DA" SNT-100-BK-G 5680.48,120 r180 top value=1x2
SH-J18 "969102-0000-DA" SNT-100-BK-G 1140,2800 r180 top value=1x2
SH-J20 "969102-0000-DA" SNT-100-BK-G 6160,2755 r90 top value=1x2
SH-J21 "969102-0000-DA" SNT-100-BK-G 3834.7,80 r180 top value=1x2
SH-J22 "969102-0000-DA" SNT-100-BK-G 6355,2360 r90 top value=1x2
TP1 "TESTPOINT_PIGTAIL" TESTPOINT_PIGTAIL 4200,1140 r180 top
TP2 "TESTPOINT_PIGTAIL" TESTPOINT_PIGTAIL 4180,2450 r90 top
TP3 "TESTPOINT_PIGTAIL" TESTPOINT_PIGTAIL 4505,1820 r90 top
TP4 "TESTPOINT_PIGTAIL" TESTPOINT_PIGTAIL 4055,960 r180 top
TP5 "TESTPOINT_PIGTAIL" TESTPOINT_PIGTAIL 2635,2014.65 r0 top
TP6 "TESTPOINT_PIGTAIL" TESTPOINT_PIGTAIL 2625,1365 r180 top
TP7 "TESTPOINT_PIGTAIL" TESTPOINT_PIGTAIL 4825,795 r0 top
TP8 "TESTPOINT_PIGTAIL" TESTPOINT_PIGTAIL 2980,1250 r90 top
TP9 "TESTPOINT_PIGTAIL" TESTPOINT_PIGTAIL 2975,1620 r90 top
TP10 "TESTPOINT_PIGTAIL" TESTPOINT_PIGTAIL 3735,870 r270 top
TP11 "TESTPOINT_PIGTAIL" TESTPOINT_PIGTAIL 3875,785 r180 top
TP12 "TESTPOINT_PIGTAIL" TESTPOINT_PIGTAIL 2130,510 r90 top
TP13 "TESTPOINT_PIGTAIL" TESTPOINT_PIGTAIL 130,1870 r180 top
TP14 "TESTPOINT_PIGTAIL" TESTPOINT_PIGTAIL 130,2390 r0 top
TP15 "TESTPOINT_PIGTAIL" TESTPOINT_PIGTAIL 6115,2450 r0 top
TP16 "TESTPOINT_PIGTAIL" TESTPOINT_PIGTAIL 6355,1520 r180 top
TP17 "TESTPOINT_PIGTAIL" TESTPOINT_PIGTAIL 3480,1630 r270 top
TP18 "TESTPOINT_PIGTAIL" TESTPOINT_PIGTAIL 5895,1105 r0 top
TP19 "TESTPOINT_PIGTAIL" TESTPOINT_PIGTAIL 4685,795 r0 top
TP20 "TESTPOINT_PIGTAIL" TESTPOINT_PIGTAIL 4975,2250 r180 top
TP21 "TESTPOINT_PIGTAIL" TESTPOINT_PIGTAIL 2980,1830 r180 top
TP22 "TESTPOINT_PIGTAIL" TESTPOINT_PIGTAIL 5450,1285 r270 top
TP23 "TESTPOINT_PIGTAIL" TESTPOINT_PIGTAIL 5260,1745 r0 top
TP24 "TESTPOINT_PIGTAIL" TESTPOINT_PIGTAIL 5355,105 r270 top
TP25 "TESTPOINT_PIGTAIL" TESTPOINT_PIGTAIL 6075,955 r180 top
TP26 "TESTPOINT_PIGTAIL" TESTPOINT_PIGTAIL 2155,840 r270 top
TP27 "TESTPOINT_PIGTAIL" TESTPOINT_PIGTAIL 1070,2470 r180 top
TP28 "TESTPOINT_PIGTAIL" TESTPOINT_PIGTAIL 4550,3050 r270 top
TP29 "TESTPOINT_PIGTAIL" TESTPOINT_PIGTAIL 4960,2590 r270 top
TP30 "TESTPOINT_PIGTAIL" TESTPOINT_PIGTAIL 6080,580 r0 top
TP31 "TESTPOINT" TP_SM_1MM 4460,895 r90 top
U1 "TMP116AIDRVR" DRV0006A 4540,1460 r90 top
U2 "TMP116AIDRVR" DRV0006A 3920,2352 r180 top
U3 "TPS92515HVDGQR" DGQ0010E_N 4340,1455 r90 top
U4 "DAC7311IDCKR" DCK0006A_N 4685,1165 r90 top
U6 "SN74LVC1G02DRLR" DRL0005A 3900,2670 r90 top
U7 "SN74LVC1G175DRYR" DRY0006A 4140,2720 r270 top
U8 "INA169NA/3K" DBV0005A_N 3400,960 r270 top
U9 "TPS7A4101DGNR" DGN0008B_N 3595,1350 r0 top
U10 "TPS92561DGNR" DGN0008D_N 3075,1405 r0 top
U11 "UCC27511DBVR" DBV0006A_N 2810,1710 r0 top
U12 "SN74LVC1G175DRYR" DRY0006A 4320,830 r270 top
U13 "TLV3201AIDCKR" DCK0005A_N 3680.31,670 r180 top
U14 "TLV3201AIDCKR" DCK0005A_N 4290,655 r180 top
U15 "TMP116AIDRVR" DRV0006A 1985,2780 r0 top
U16 "TMP116AIDRVR" DRV0006A 495,1755 r90 top
U17 "SN74LVC1G14DRLR" DRL0005A 1900,390 r90 top
U18 "UCC27511DBVR" DBV0006A_N 1875,620 r90 top
U19 "SN74LVC1G17DCKR" DCK0005A_N 528.11,2650 r0 top
U20 "UCC27511DBVR" DBV0006A_N 786.36,2635 r0 top
U21 "MSP430F5172IRSBR" RSB0040B 3185,2290 r180 top
U22 "ISOW7842DWER" DWE0016A 5480,402.41 r0 top
U23 "TPD1E10B06DPYR" DPY0002A 6225,550 r270 top
U24 "TPD1E10B06DPYR" DPY0002A 6230,860 r270 top
U25 "TPD1E10B06DPYR" DPY0002A 6225,410 r90 top
U26 "TPD1E10B06DPYR" DPY0002A 6230,1005 r90 top
U27 "TPS26602PWPR" PWP0016H_N 5385,2355 r0 top
U28 "DAC082S085CISD/NOPB" SDA10A 3585,1785 r90 top
U29 "LP5907MFX-3.3/NOPB" DBV0005A_N 5040,2040 r90 top
U30 "REF3025AIDBZR" DBZ0003A_N 3175,1810 r270 top
U31 "LM5165DRCR" DRC0010J 5280,990 r270 top
U32 "TPS22810DRV" DRV0006A 5035,1680 r180 top
U33 "TLV3201AIDCKR" DCK0005A_N 4375,2750 r0 top
ZZ1 "This Assembly Note is for PCB labels only" AssemblyNoteLabel 160,4610 r0 top
ZZ2 "These assemblies are ESD sensitive, ESD precautions shall be observed." AssemblyNote 160,4510 r0 top
ZZ3 "These assemblies must be clean and free from flux and all contaminants. Use of no clean flux is not acceptable." AssemblyNote 160,4410 r0 top
ZZ4 "These assemblies must comply with workmanship standards IPC-A-610 Class 2, unless otherwise specified." AssemblyNote 160,4320 r0 top
ZZ5 "Place SH3 onto J3 Pin 1 - 2" AssemblyNote 160,4110 r0 top
ZZ6 "Place SH5 onto J5 Pin 1 - 2" AssemblyNote 160,4010 r0 top
ZZ7 "Place SH8 onto J8 Pin 1 - 2" AssemblyNote 160,3910 r0 top
ZZ8 "Place SH11 onto J11 Pin 2 - 3" AssemblyNote 160,3810 r0 top
ZZ9 "Place SH12 onto J12 Pin 1 - 2" AssemblyNote 160,3710 r0 top
ZZ10 "Place SH17 onto J17 Pin 1 - 2" AssemblyNote 1780,4110 r0 top
ZZ11 "Place SH18 onto J18 Pin 1 - 2" AssemblyNote 1780,4010 r0 top
ZZ12 "Place SH20 onto J20 Pin 7 - 8" AssemblyNote 1780,3910 r0 top
ZZ13 "Place SH21 onto J21 Pin 1 - 2" AssemblyNote 1780,3810 r0 top
ZZ14 "Place SH22 onto J22 Pin 1 - 2" AssemblyNote 1780,3710 r0 top

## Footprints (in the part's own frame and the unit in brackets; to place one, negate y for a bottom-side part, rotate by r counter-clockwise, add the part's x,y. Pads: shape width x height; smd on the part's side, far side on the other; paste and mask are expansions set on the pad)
0402 [mm] "0402 from SM-752 data"
  rect 0.8x0.6 smd: 1(-0.6,0) 2(0.6,0)
  silkscreen extent -1.22,-0.52 1.22,0.52, body extent -0.55,-0.3 0.55,0.3, height 0.6
0603 [mm] "0603 from SM-752 data"
  rect 1x0.95 smd: 1(-0.8,0) 2(0.8,0)
  silkscreen extent -1.52,-0.69 1.52,0.69, body extent -0.87,-0.47 0.87,0.47, height 1
0603_120 [mm] "0603_120"
  rect 1x1 smd: 1(-0.8,0) 2(0.8,0)
  silkscreen extent -0.1,-0.58 0.1,0.58, body extent -0.87,-0.48 0.87,0.48, height 1.2
0603_HR [mm] "0603"
  rect 0.5x0.9 smd: 1(-0.75,0) 2(0.75,0)
  silkscreen extent -1.35,-0.75 1.35,0.77, body extent -0.82,-0.47 0.82,0.47, height 0.5
0603_HV [mil] "Ernesto recommended land pattern.  26 mil between pads."
  rect 30x30 smd: 1(-28,0) 2(28,0)
  silkscreen extent -52,-24 52,24, body extent -34,-19 34,19, height 39
0603S [mil]
  rect 20x35 smd: 1(-30,0) 2(30,0)
  silkscreen extent -10,-17 10,17, body extent -34,-19 34,19, height 39
0805_HV [mil] "0805 with 30mil clearance between pads"
  rect 50x63 smd: 1(-40,0) 2(40,0)
  silkscreen extent -74,-40 74,40, body extent -43,-29 43,29, height 57
1206 [mm] "1206 from SM-752 data"
  rect 1.3x1.85 smd: 1(-1.45,0) 2(1.45,0)
  silkscreen extent -2.4,-1.21 2.4,1.21, body extent -1.7,-0.9 1.7,0.9, height 1.35
1206_180 [mm] "1206_180"
  rect 1.1x1.6 smd: 1(-1.7,0) 2(1.7,0)
  silkscreen extent -0.9,-1 0.9,1, body extent -1.75,-0.95 1.75,0.95, height 1.8
1210_250 [mm] "1210"
  rect 1.3x2.7 smd: 1(-1.45,0) 2(1.45,0)
  silkscreen extent -2.32,-1.57 2.32,1.57, body extent -1.7,-1.35 1.7,1.35, height 2.5
1210_270 [mm] "1210"
  rect 1.3x2.7 smd: 1(-1.45,0) 2(1.45,0)
  silkscreen extent -2.32,-1.57 2.32,1.57, body extent -1.7,-1.35 1.7,1.35, height 2.7
1806_HighSpeed [mm] "Wurth recommended land pattern"
  rrect8% 1.25x1.2 smd: 1(-2.125,0) 2(2.125,0)
  silkscreen extent -1.5,-1 1.5,1, body extent -2.25,-0.8 2.25,0.8, height 1.61
9080032809 [mil] "Hex Nuts: M3 X .5MM pitch DIN 934 A2 - 304 Stainless"
  body extent -115,-100 115,100, height 110
AssemblyNote [mil] "Assembly Note"
AssemblyNoteLabel [mil] "Assembly Note for PCB Labels"
CLF7045 [mm] "TDK"
  rect 1.7x2.2 smd: 1(-3.05,0) 2(3.05,0)
  silkscreen extent -3.7,-3.55 3.7,3.55, body extent -3.7,-3.55 3.7,3.55, height 4.8
CONN_PEC04DAAN [mm] "SULLINS"
  rect 1.65x1.65 hole 1.016 mask+0: 1(-3.81,-1.27)
  round 1.65 hole 1.016 mask+0: 2(-3.81,1.27) 3(-1.27,-1.27) 4(-1.27,1.27) 5(1.27,-1.27) 6(1.27,1.27) 7(3.81,-1.27) 8(3.81,1.27)
  silkscreen extent -5.21,-3.38 5.08,2.54, body extent -5.08,-2.54 5.08,2.54, height 8.38
DBV0005A_N [mm] "SOT23, 5-Leads, Body 2.9x1.6mm, Pitch 0.95mm, Lead Span 2.8mm, IPC Medium Density"
  rrect17% 1x0.6 smd: 1(-1.375,0.95) 2(-1.375,0) 3(-1.375,-0.95) 4(1.375,-0.95) 5(1.375,0.95)
  silkscreen extent -1.63,-1.55 0.38,1.55, body extent -1.42,-1.46 1.42,1.46, height 1.09
DBV0006A_N [mm] "SOT23, 6-Leads, Body 2.9x1.6mm, Pitch 0.95mm, Lead Span 2.8mm, IPC Medium Density"
  rrect17% 1x0.6 smd: 1(-1.375,0.95) 2(-1.375,0) 3(-1.375,-0.95) 4(1.375,-0.95) 5(1.375,0) 6(1.375,0.95)
  silkscreen extent -1.68,-1.55 0.5,1.55, body extent -1.42,-1.46 1.42,1.46, height 1.12
DBZ0003A_N [mm] "SOT23, 3-Leads, Body 2.9x1.3mm, Pitch 0.95mm, Lead Span 2.4mm, IPC Medium Density"
  rrect17% 1x0.6 smd: 1(-1.2,0.95) 2(-1.2,-0.95) 3(1.2,0)
  silkscreen extent -1.65,-1.5 0.7,1.5, body extent -1.26,-1.46 1.26,1.46, height 0.98
DCK0005A_N [mm] "SOT353, 5-Leads, Body 2x1.3mm, Pitch 0.65mm, Lead Span 2.1mm, IPC Medium Density"
  rrect25% 0.85x0.4 smd: 1(-1.125,0.65) 2(-1.125,0) 3(-1.125,-0.65) 4(1.125,-0.65) 5(1.125,0.65)
  silkscreen extent -1.48,-1.02 0.55,1.1, body extent -1.14,-1 1.14,1, height 0.95
DCK0006A_N [mm] "SOT23, 6-Leads, Body 2x1.3mm, Pitch 0.65mm, Lead Span 2.1mm, IPC Medium Density"
  rrect25% 0.85x0.4 smd: 1(-1.125,0.65) 2(-1.125,0) 3(-1.125,-0.65) 4(1.125,-0.65) 5(1.125,0) 6(1.125,0.65)
  silkscreen extent -1.5,-1.09 0.51,1.09, body extent -1.14,-1 1.14,1, height 0.95
DGN0008B_N [mm] "TSOP, 8-Leads, Body 3x3mm, Pitch 0.65mm, Thermal Pad 1.92x1.60mm, IPC Medium Density"
  rrect100% 1.35x0.45 smd: 1(-2.225,0.975) 2(-2.225,0.325) 3(-2.225,-0.325) 4(-2.225,-0.975) 5(2.225,-0.975) 6(2.225,-0.325) 7(2.225,0.325) 8(2.225,0.975)
  rrect5% 1.88x1.98 smd: 9(0,0)
  silkscreen extent -2.7,-1.55 0.95,1.55, body extent -2.46,-1.5 2.46,1.5, height 1.1
DGN0008D_N [mm] "TSOP, 8-Leads, Body 3x3mm, Pitch 0.65mm, Thermal Pad 1.89x1.57mm, IPC Medium Density"
  rrect100% 1.35x0.45 smd: 1(-2.225,0.975) 2(-2.225,0.325) 3(-2.225,-0.325) 4(-2.225,-0.975) 5(2.225,-0.975) 6(2.225,-0.325) 7(2.225,0.325) 8(2.225,0.975)
  rrect6% 1.57x1.89 smd: 9(0,0)
  silkscreen extent -2.73,-1.55 0.95,1.55, body extent -2.46,-1.5 2.46,1.5, height 1.1
DGQ0010E_N [mm] "TSSOP, 10-Leads, Body 3x3mm, Pitch 0.5mm, Thermal Pad 1.83x2.1mm, IPC Medium Density"
  rrect5% 1.83x2.1 on Top Solder: 0(0,0)
  rrect5% 1.83x2.1 on Top Paste: 0(0,0)
  rrect100% 1.35x0.3 smd: 1(-2.225,1) 2(-2.225,0.5) 3(-2.225,0) 4(-2.225,-0.5) 5(-2.225,-1) 6(2.225,-1) 7(2.225,-0.5) 8(2.225,0) 9(2.225,0.5) 10(2.225,1)
  rect 2.2x3.1 smd paste-1.1 mask-1.1: 11(0,0)
  silkscreen extent -2.73,-1.7 0.9,1.7, body extent -2.46,-1.5 2.46,1.5, height 0.95
DNH0008A [mm] "8 pin VSONP, 0.65 mm pitch"
  rrect50% 0.7x0.4 smd paste-0.05 mask-0.05: 1(-1.55,0.975) 2(-1.55,0.325) 3(-1.55,-0.325) 4(-1.55,-0.975) 5(1.55,-0.975) 6(1.55,-0.325) 7(1.55,0.325) 8(1.55,0.975)
  rrect14% 0.705x1.125 on Top Paste: 9(-0.208,0.662) 9(-0.208,-0.663) 9(0.697,0.662) 9(0.697,-0.663)
  rrect6% 1.775x2.45 on Top Solder: 9(0.327,0)
  rrect4% 2.51x2.55 smd paste-1.5 mask-1.5: 9(0.645,0)
  rect 0.5x0.3 on Top Solder: 9(1.175,0.975) 9(1.175,-0.325) 9(1.175,0.325) 9(1.175,-0.975)
  silkscreen extent -1.62,-1.7 1.62,1.7, body extent -1.65,-1.65 1.65,1.66, height 0.91
DO-219AB [mm] "Vishay Semiconductor"
  rect 1.4x1.3 smd: 1(-1.45,0) 2(1.45,0)
  silkscreen extent -2.67,-1.3 0.5,1.3, body extent -1.45,-0.95 1.45,0.95, height 1.08
DPY0002A [mm] "R-PX2SON-N2"
  rect 0.6x0.5 smd: 1(-0.5,0) 2(0.5,0)
  body extent -0.55,-0.35 0.55,0.35, height 0.4
DRC0010J [mm] "SON, 10-Leads, Body 3x3mm, Pitch 0.5mm, Thermal Pad 2.4x1.65mm, TI Recommended"
  rrect40% 0.6x0.25 smd: 1(-1.4,1) 2(-1.4,0.5) 3(-1.4,0) 4(-1.4,-0.5) 5(-1.4,-1) 6(1.4,-1) 7(1.4,-0.5) 8(1.4,0) 9(1.4,0.5) 10(1.4,1)
  rrect40% 0.25x0.34 on Top Paste: 11(-0.25,1.53) 11(-0.25,-1.53) 11(0.25,1.53) 11(0.25,-1.53)
  rrect9% 1.5x1.06 on Top Paste: 11(0,0.63) 11(0,-0.63)
  rrect12% 1.65x2.4 smd paste-1 mask-2: 11(0,0)
  Top Layer region: -0.775,-1.25 -0.425,-1.25 -0.425,-1.65 -0.417,-1.688 -0.396,-1.721 -0.363,-1.742 -0.325,-1.75 -0.325,-1.75 -0.325,-1.75 -0.175,-1.75 -0.175,-1.75 -0.137,-1.742 -0.104,-1.721 -0.083,-1.688 -0.075,-1.65 -0.075,-1.65 -0.075,-1.25 0.075,-1.25 0.075,-1.65 0.083,-1.688 0.104,-1.721 0.137,-1.742 0.175,-1.75 0.175,-1.75 0.175,-1.75 0.325,-1.75 0.325,-1.75 0.363,-1.742 0.396,-1.721 0.417,-1.688 0.425,-1.65 0.425,-1.65 0.425,-1.25 0.775,-1.25 0.813,-1.242 0.846,-1.221 0.867,-1.188 0.875,-1.15 0.875,-1.15 0.875,1.15 0.867,1.188 0.846,1.221 0.813,1.242 0.775,1.25 0.775,1.25 0.425,1.25 0.425,1.65 0.417,1.688 0.396,1.721 0.363,1.742 0.325,1.75 0.325,1.75 0.175,1.75 0.137,1.742 0.104,1.721 0.083,1.688 0.075,1.65 0.075,1.65 0.075,1.25 -0.075,1.25 -0.075,1.65 -0.083,1.688 -0.104,1.721 -0.137,1.742 -0.175,1.75 -0.175,1.75 -0.325,1.75 -0.363,1.742 -0.396,1.721 -0.417,1.688 -0.425,1.65 -0.425,1.65 -0.425,1.25 -0.775,1.25 -0.813,1.242 -0.846,1.221 -0.867,1.188 -0.875,1.15 -0.875,1.15 -0.875,-1.15 -0.867,-1.188 -0.846,-1.221 -0.813,-1.242 -0.775,-1.25
  silkscreen extent -1.63,-1.63 1.63,1.63, body extent -1.5,-1.5 1.5,1.5, height 0.77
DRL0005A [mm] "SOTFL, 5-Flat Leads, Body 1.2x1.6x0.6mm, Pitch 0.5mm, TI recommended"
  rrect33% 0.67x0.3 smd: 1(-0.74,0.5) 2(-0.74,0) 3(-0.74,-0.5) 4(0.74,-0.5) 5(0.74,0.5)
  silkscreen extent -0.9,-0.95 0.5,0.95, body extent -0.85,-0.85 0.85,0.85, height 0.62
DRV0006A [mm] "SON, 6-Leads, Body 2x2mm, Pitch 0.65mm, Thermal Pad 1.6x1mm, TI Recommended"
  rrect33% 0.45x0.3 smd: 1(-0.975,0.65) 2(-0.975,0) 3(-0.975,-0.65) 4(0.975,-0.65) 5(0.975,0) 6(0.975,0.65)
  rrect14% 1x0.7 on Top Paste: 7(0,0.45) 7(0,-0.45)
  rrect10% 1x1.6 smd paste-0.5: 7(0,0)
  silkscreen extent -1.05,-1.2 1.05,1.2, body extent -1.05,-1.05 1.05,1.05, height 0.81
DRY0006A [mm] "PSON, 6-Leads, Body 1x1.45mm, Pitch 0.5mm, TI Recommended"
  rect 0.35x0.2 smd: 1(-0.275,0.5)
  rect 0.3x0.2 smd: 2(-0.3,0) 3(-0.3,-0.5) 4(0.3,-0.5) 5(0.3,0) 6(0.3,0.5)
  silkscreen extent -0.5,-0.85 0.2,0.85, body extent -0.53,-0.75 0.53,0.75, height 0.61
DWE0016A [mm] "SOIC, 16-Leads, Body 10.5x7.6mm, Pitch 1.27mm"
  rrect17% 1.65x0.6 smd: 1(-4.875,4.445) 2(-4.875,3.175) 3(-4.875,1.905) 4(-4.875,0.635) 5(-4.875,-0.635) 6(-4.875,-1.905) 7(-4.875,-3.175) 8(-4.875,-4.445) 9(4.875,-4.445) 10(4.875,-3.175) 11(4.875,-1.905) 12(4.875,-0.635) 13(4.875,0.635) 14(4.875,1.905) 15(4.875,3.175) 16(4.875,4.445)
  silkscreen extent -3.8,-5.25 3.8,5.6, body extent -5.17,-5.15 5.17,5.15, height 2.59
Fairchild_SOD-523F [mm] "SMD, 2-Leads, Body 1.2x0.8mm"
  rect 0.8x0.5 smd: 1(-1,0) 2(1,0)
  silkscreen extent -2.03,-0.65 1.4,0.65, body extent -0.65,-0.45 0.65,0.45, height 0.7
FCC_disclaimer [mil]
FE_ICK_S10X10X6_5 [mil] "Heat Sink, 10x10x6.5mm"
  silkscreen extent -197,-197 197,197, body extent -197,-197 197,197, height 256
Fiducial10-20 [mm]
  round 1 smd mask+0.5: 1(0,0)
  Top Layer keep-out circle w1.178: c0,0 r0.5
IEC_Caution_Small [mil]
  silkscreen extent -107,-93 107,92
IEC_HotSurface_Small [mil]
  silkscreen extent -107,-93 107,92
Keystone_1902C#1 [mil] "Hex Standoff, 4-40 threaded, nylon"
  round 1 on Mech4: 0(0,0)
  body extent -145,-126 146,126, height 501
Keystone_1902C#2 [mil] "Hex Standoff, 4-40 threaded, nylon"
  body extent -145,-126 146,126, height 501
Keystone_4802 [mm] "Hex M/F Standoff"
  round 0.05 on Mech3: 1(0,0)
  body extent -3.18,-3.67 3.17,3.67, height 12.71
KRL1220 [mm] "Susumu"
  rect 0.75x1.5 smd: 1(-1.125,0) 2(1.125,0)
  silkscreen extent -0.5,-0.85 0.5,0.85, body extent -1.1,-0.72 1.1,0.72, height 0.7
KRL1632G8m [mm] "Susumu"
  rrect12% 0.8x1.9 smd: 1(-1.6,0) 2(1.6,0)
  silkscreen extent -0.9,-1 0.9,1, body extent -1.7,-0.9 1.7,0.9, height 0.7
Label_650x200 [mil] "Thermal Transfer Label"
  silkscreen extent -325,-100 325,100, body extent -325,-100 325,100, height 1
LED_Warning [mil]
  silkscreen extent -217,-182 217,193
